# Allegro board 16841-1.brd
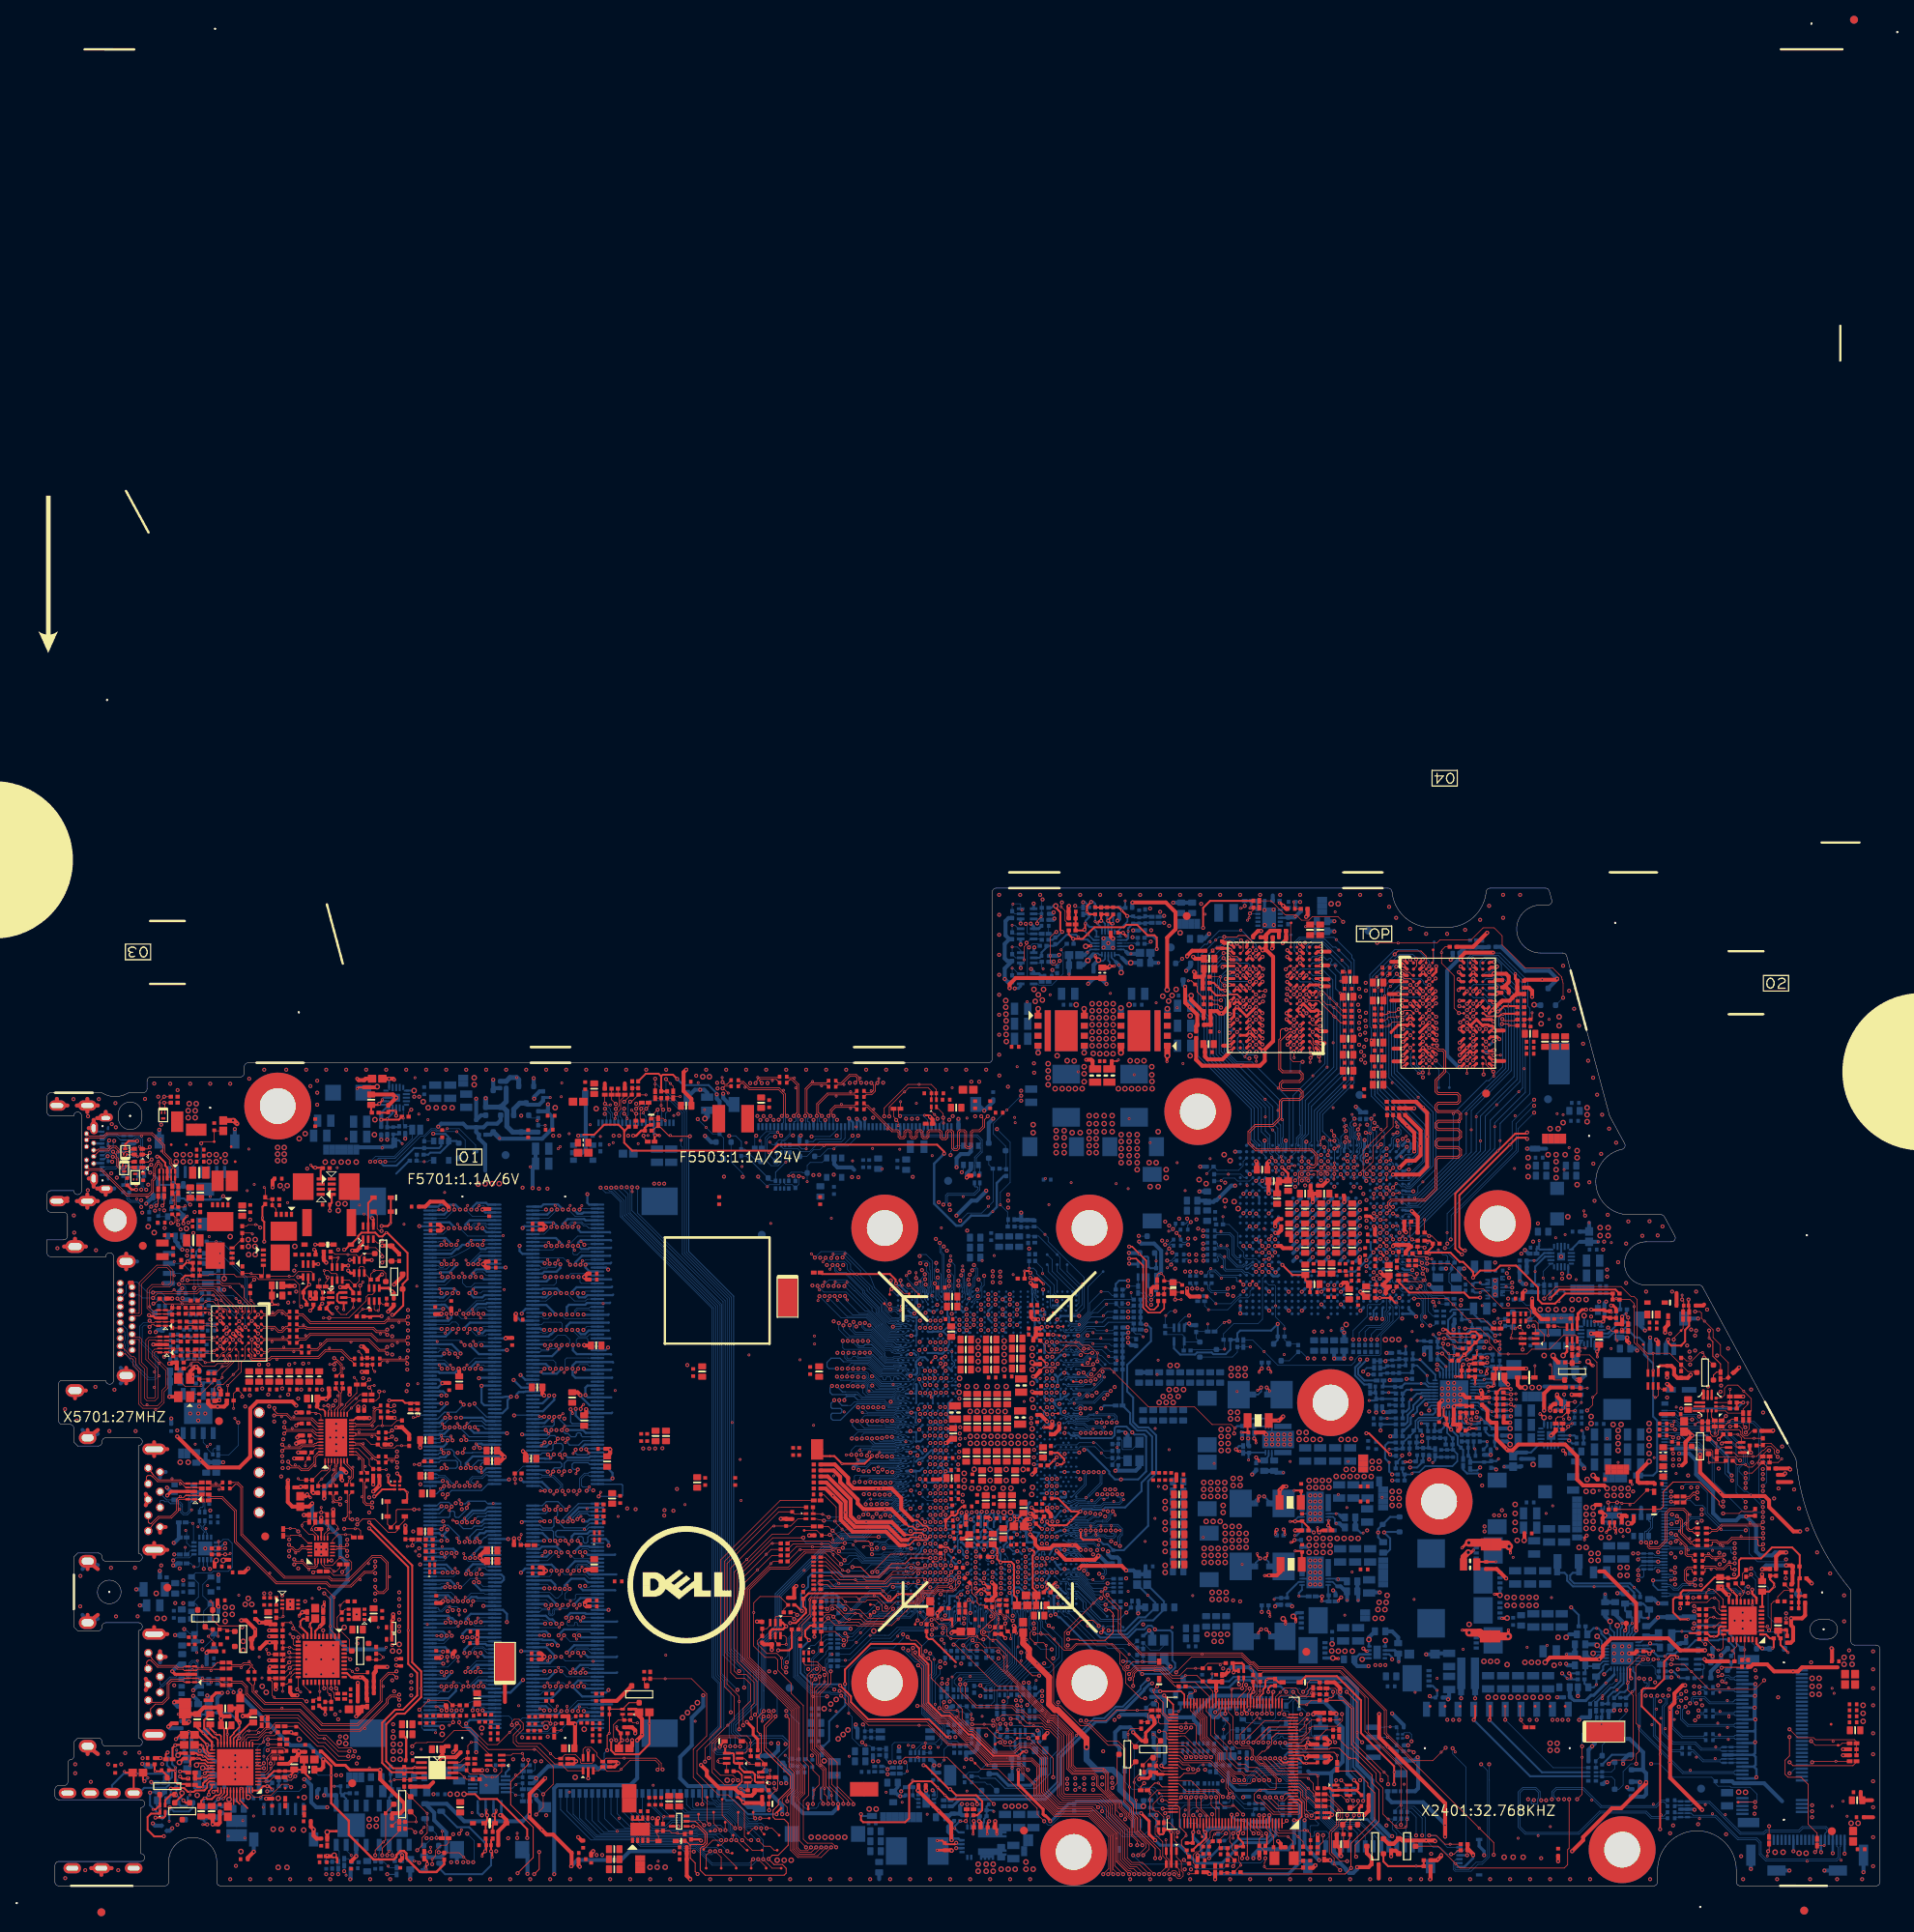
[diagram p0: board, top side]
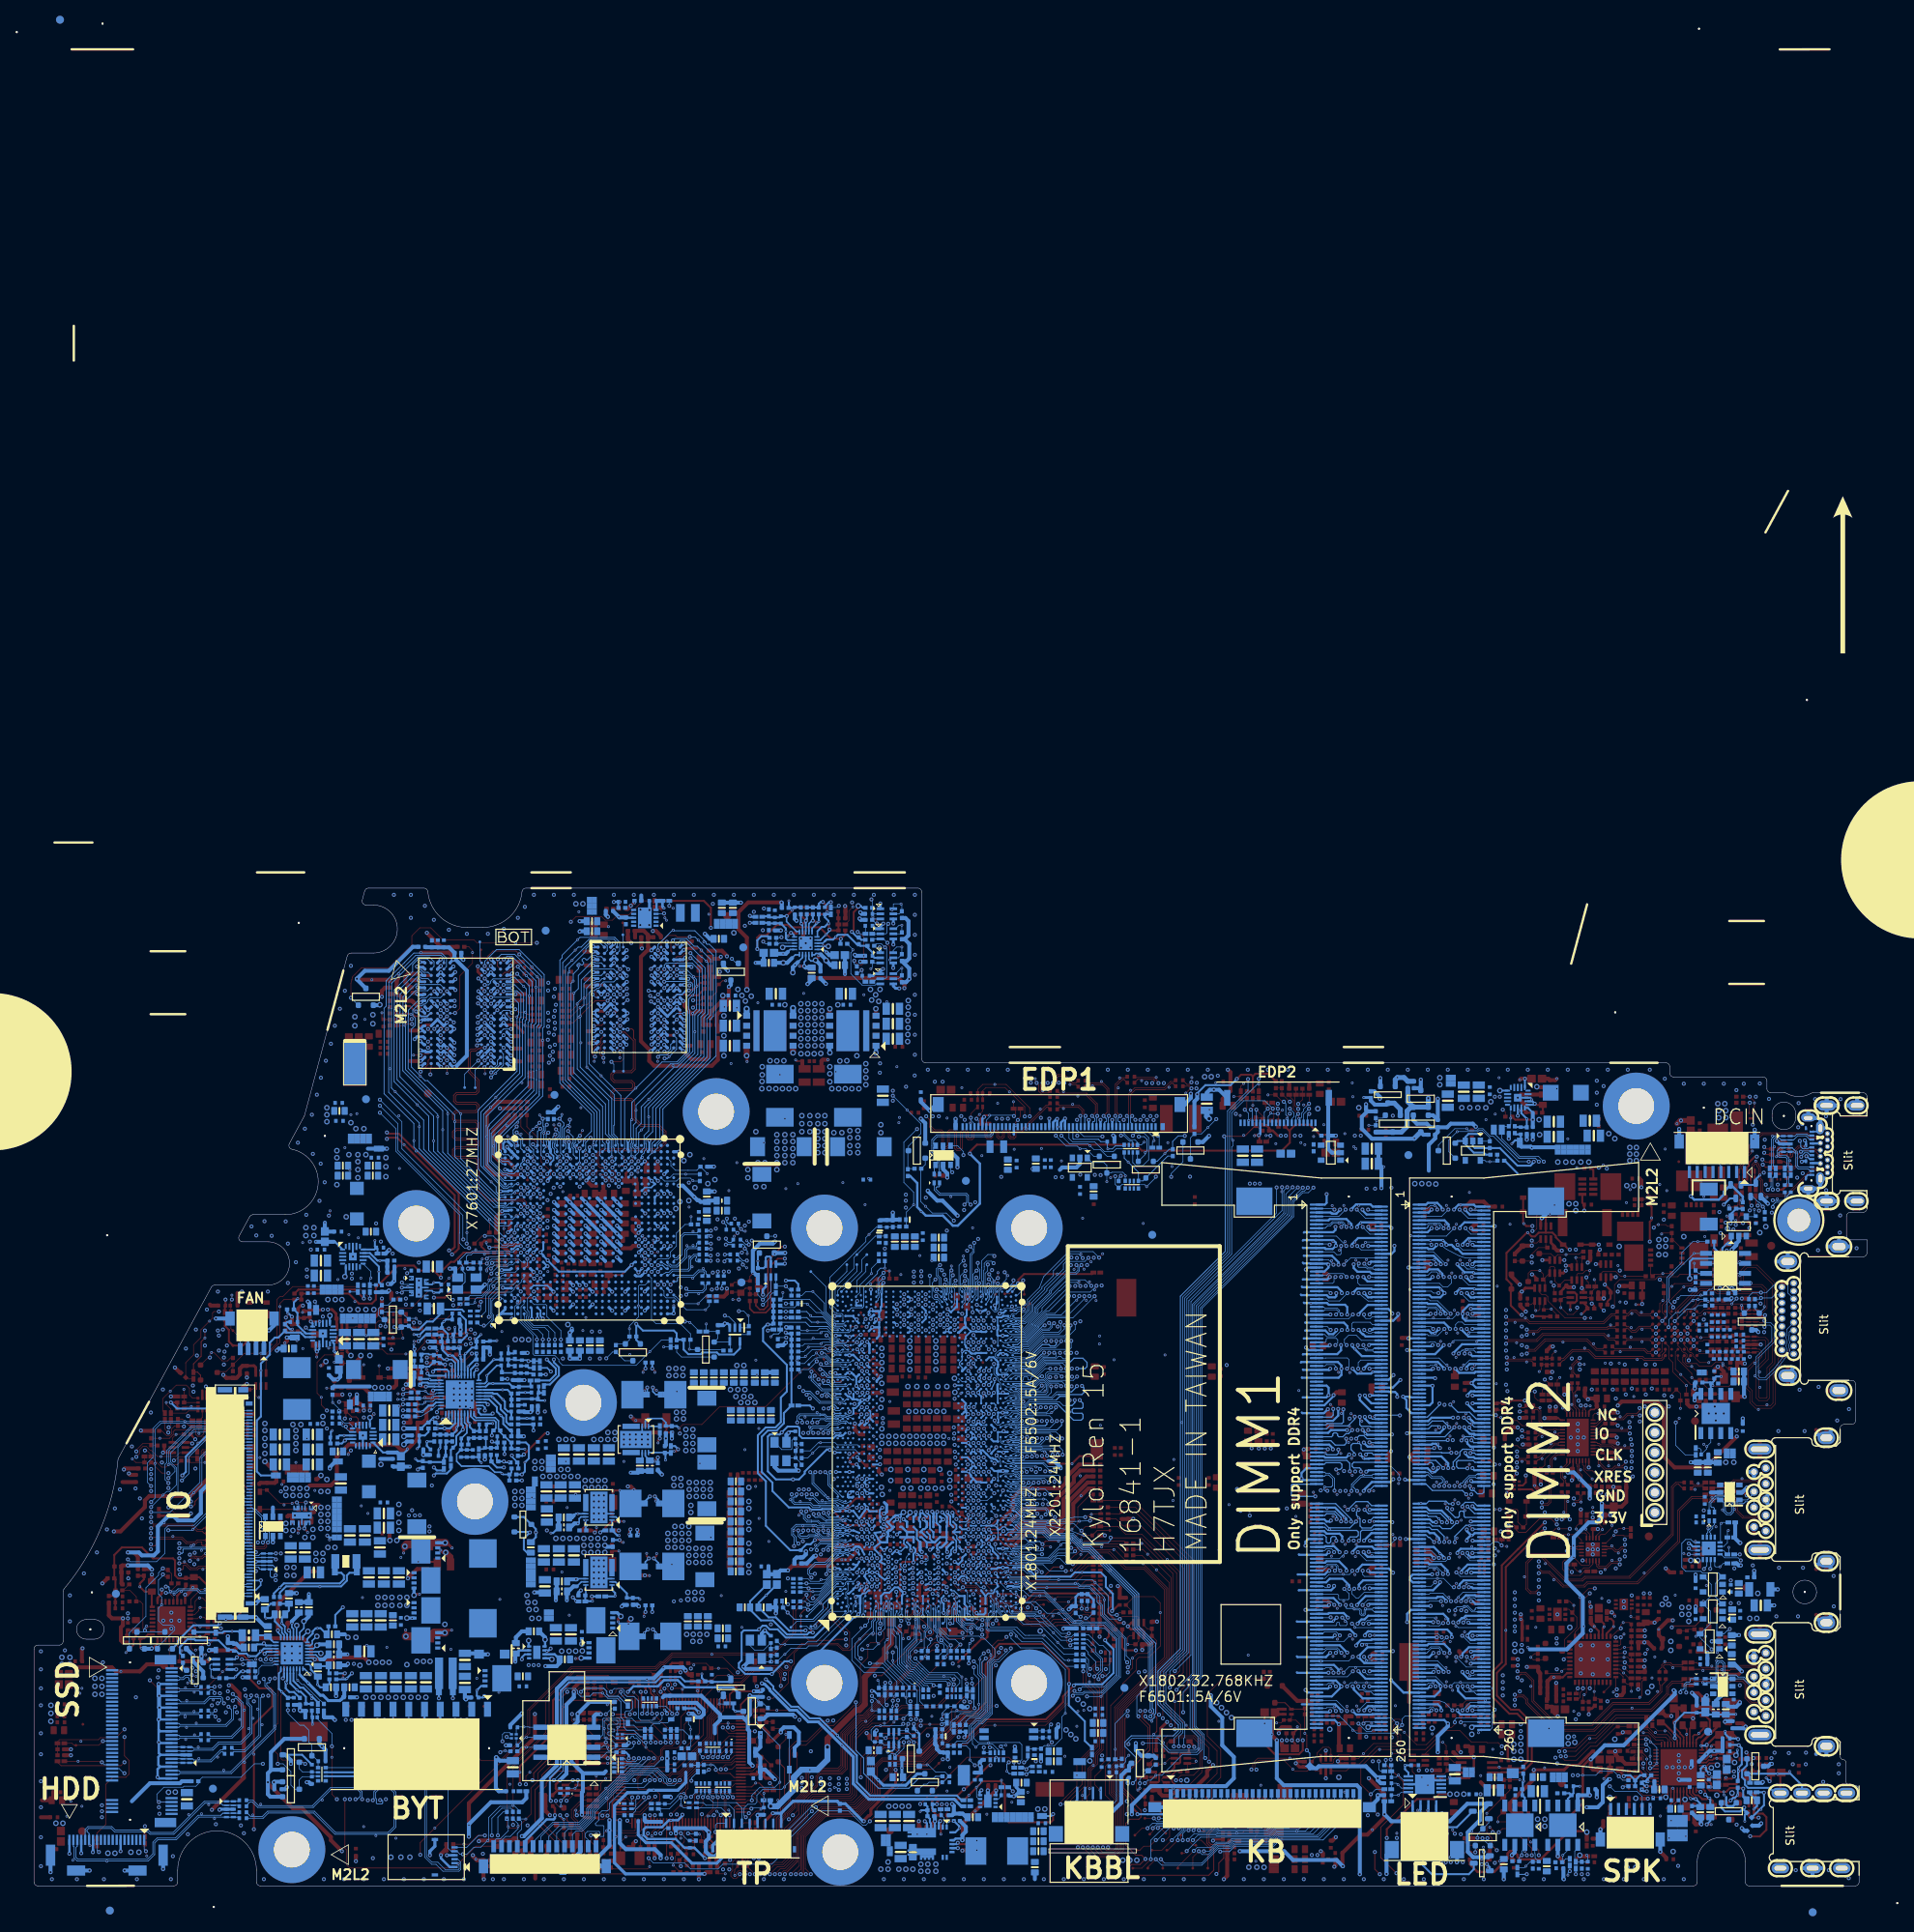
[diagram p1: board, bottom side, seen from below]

Outline 232.8 x 126.8 mm; copper layers: TOP, L2GND, L3, L4, L5VCC, L6, L7GND, BOTTOM. Coordinates in mm from the lower left corner of the outline.

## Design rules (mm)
constraint set DEFAULT: min track width 0.127, pair gap 0.102
net group AUDIO_12MIL: nets CPVEE TCH_RST#
net group AUDIO_BITCLK_50-MWS: nets CODEC_BITCLK_R HDA_BITCLK
net group CPU_RXN_C_DGPU_TXN0-DIFF1: nets CPU_RXN_C_DGPU_TXN0 CPU_RXP_C_DGPU_TXP0
net group CPU_RXN_C_DGPU_TXN1-DIFF1: nets CPU_RXN_C_DGPU_TXN1 CPU_RXP_C_DGPU_TXP1
net group CPU_RXN_C_DGPU_TXN2-DIFF1: nets CPU_RXN_C_DGPU_TXN2 CPU_RXP_C_DGPU_TXP2
net group CPU_RXN_C_DGPU_TXN3-DIFF1: nets CPU_RXN_C_DGPU_TXN3 CPU_RXP_C_DGPU_TXP3
net group DDR4_A_BA_40-MW: nets M_A_BA0 M_A_BA1
net group DDR4_A_BG_40-MW: nets M_A_BG0 M_A_BG1
net group DDR4_A_ODT10-MW: nets M_A_DIMA_ODT0 M_A_DIMA_ODT1
net group DDR4_B_BA_40-MW: nets M_B_BA0 M_B_BA1
net group DDR4_B_BG_40-MW: nets M_B_BG0 M_B_BG1
net group DDR4_B_ODT10-MW: nets M_B_DIMB_ODT0 M_B_DIMB_ODT1
net group DP_DATA0_R-DIFF1: nets DP_DATA0_N_R DP_DATA0_P_R
net group DP_DATA1_R-DIFF1: nets DP_DATA1_N_R DP_DATA1_P_R
net group DP_DATA2_R-DIFF1: nets DP_DATA2_N_R DP_DATA2_P_R
net group DP_DATA3_R-DIFF1: nets DP_DATA3_N_R DP_DATA3_P_R
net group EDP_AUX_CON-DIFF222: nets EDP_AUX EDP_AUX#
net group EDP_TX0_CON-DIFF224: nets EDP_TX0 EDP_TX0#
net group EDP_TX1_CON-DIFF278: nets EDP_TX1 EDP_TX1#
net group EDP_TX3_CON-DIFF230: nets EDP_TX3 EDP_TX3#
net group FAN_TACH: nets FAN1_TACH FAN_TACH1_C
net group HDMI_AUX_L-DIFF1: nets HDMI_AUXN_L HDMI_AUXP_L
net group HDMI_AUX_R-DIFF1: nets HDMI_AUXN_R HDMI_AUXP_R
net group HDMI_CLK-DIFF1: nets HDMI_CLK#_C HDMI_CLK_C
net group HDMI_CLK_R_C-DIFF: nets HDMI_CLK#_R_C HDMI_CLK_R_C
net group HDMI_DATA0_C-DIFF1: nets HDMI_DATA0#_C HDMI_DATA0_C
net group HDMI_DATA1_C-DIFF1: nets HDMI_DATA1#_C HDMI_DATA1_C
net group HDMI_DATA1_L_C-DIFF1: nets HDMI_DATA1#_L_C HDMI_DATA1_L_C
net group HDMI_DATA2_C-DIFF1: nets HDMI_DATA2#_C HDMI_DATA2_C
net group HDMI_DATA2_L_C-DIFF1: nets HDMI_DATA2#_L_C HDMI_DATA2_L_C
net group I2C_MUX_50: nets I2C_CLK_PD_MUX I2C_DATA_PD_MUX
net group MUX_INB_: nets MUX_INB_N MUX_INB_P
net group PCH_DPC_N0_CON-DIFF267: nets PCH_DPC_N0_C PCH_DPC_P0_C
net group PCH_DPC_N1_CON-DIFF266: nets PCH_DPC_N1_C PCH_DPC_P1_C
net group PCH_DPC_N2_CON-DIFF265: nets PCH_DPC_N2_C PCH_DPC_P2_C
net group PCH_DPC_N3_CON-DIFF264: nets PCH_DPC_N3_C PCH_DPC_P3_C
net group PCIE_TX_CON9-DIFF1: nets PCIE_TX_CON_N9 PCIE_TX_CON_P9
net group PCIE_TX_CON10-DIFF1: nets PCIE_TX_CON_N10 PCIE_TX_CON_P10
net group PCIE_TX_CON11-DIFF1: nets PCIE_TX_CON_N11 PCIE_TX_CON_P11
net group PCIE_TX_CPU6-DIFF1: nets PCIE_TX_CPU_N6 PCIE_TX_CPU_P6
net group POWER_15M: nets Q6205_Q Q6502_D
net group SATA_RX_CON0-DIFF269: nets SATA_RXN0_R SATA_RXP0_R
net group SIGNAL_V_F_8_OHM-MW: nets CFG3 XDP_DBRESET#
net group SIGNAL_V_F_10MIL: nets BEEP FAN_TACH1
net group SIGNAL_V_F_16.5_OHM-MWS: nets PCH_SMBCLK PCH_SMBDATA
net group SIGNAL_V_F_16.5_SVID-MWS: nets VR_SVID_CLK VR_SVID_DATA
net group SMBUS_10MIL: nets PBAT_SMBCLK1 PBAT_SMBDAT1
net group TYPEC_CON_RX1-DIFF270: nets TYPEC_CON_RXN1 TYPEC_CON_RXP1
net group TYPEC_CON_RX2-DIFF271: nets TYPEC_CON_RXN2 TYPEC_CON_RXP2
net group TYPEC_DPB_AUX_CON-DIFF259: nets DPB_AUXN_C DPB_AUXP_C
net group USB30_RX_C1-DIFF241: nets USB30_RXDN1_C USB30_RXDP1_C
net group USB30_RX_CON4-DIFF240: nets USB30_RX_CPU_N4_C USB30_RX_CPU_P4_C
net group USB30_TX_CON4-DIFF239: nets USB30_TX_CPU_N4_C USB30_TX_CPU_P4_C
net group USB_CON1-DIFF248: nets USB20_DN1_C USB20_DP1_C
net group USB_CON4-DIFF257: nets USB_CAMERA_N USB_CAMERA_P
net group USB_CON5-DIFF252: nets USB_CPU_PN5_C USB_CPU_PP5_C
net group USB_CON7-DIFF251: nets USB_CPU_PN7_C USB_CPU_PP7_C
net group XDP_BPM-MW: nets XDP_BPM0 XDP_BPM1
net group XDP_TCLK-MWS: nets XDP_TCK_JTAGX XDP_TCLK
net group AUDIO_BEEP_10MIL: nets AUD_HP1_JACK_L AUD_HP1_JACK_L1 AUD_HP1_JACK_R AUD_HP1_JACK_R1 AUD_PC_BEEP AUD_PC_BEEP_C AUD_PC_BEEP_R AUD_PORTA_L_R_B AUD_PORTA_R_R_B AUD_SENSE AUD_SENSE_A AUD_VREF CBN CBP HDA_SPKR_R JACK_PLUG JACK_PLUG_DET KBC_BEEP_R LINE1-L_C LINE1-L_R LINE1_L LINE1_R MIC2_VREFO_L MIC2_VREFO_R SPKR
net group AUDIO_DIGITAL_50-MWS: nets CODEC_SDOUT_R HDA_CODEC_SDIN0 HDA_RST# HDA_SDOUT HDA_SYNC SPK_I2C_CLK SPK_I2C_DATA
net group CFG_50-MWS: nets CFG4
net group CLK_50-MWS: nets SPI_CK_OUT_HDMI SPI_CLK_CPU SPI_CLK_ROM SPI_CLK_ROM_R SPI_CLK_ROM_TPM2 SUS_CLK SUSCLK
net group CLK_50R-MW: nets ESPI_CLK PCH_ESPI_CLK PEXTSTCLK_OUT PEXTSTCLK_OUT# VIDEO_CLK_XTAL_SS
net group COMP_20MIL: nets CPU_POPIRCOMP CSI2_COMP EMMC_RCOMP EOPIO_RCOMP PCH_POPIRCOMP SD_RCOMP SM_RCOMP_0 SM_RCOMP_1 SM_RCOMP_2 USBCOMP XCLK_BIASREF
net group CPU_50-MWS: nets H_PROCHOT#_R PQ4405_3 PWR_CHG_PROCHOT#
net group CPU_50R-MW: nets VGA_CORE_VID
net group DDR4_A_CMD_40-MW: nets M_A_A0 M_A_A1 M_A_A2 M_A_A3 M_A_A4 M_A_A5 M_A_A6 M_A_A7 M_A_A8 M_A_A9 M_A_A10 M_A_A11 M_A_A12 M_A_A13 M_A_A14 M_A_A15 M_A_A16 M_A_ACT_N M_A_ALERT_N M_A_PARITY
net group DDR4_A_DATA_00_50-MW: nets M_A_DQ0 M_A_DQ1 M_A_DQ2 M_A_DQ3 M_A_DQ4 M_A_DQ5 M_A_DQ6 M_A_DQ7
net group DDR4_A_DATA_01_50-MW: nets M_A_DQ8 M_A_DQ9 M_A_DQ10 M_A_DQ11 M_A_DQ12 M_A_DQ13 M_A_DQ14 M_A_DQ15
net group DDR4_A_DATA_02_50-MW: nets M_A_DQ16 M_A_DQ17 M_A_DQ18 M_A_DQ19 M_A_DQ20 M_A_DQ21 M_A_DQ22 M_A_DQ23
net group DDR4_A_DATA_03_50-MW: nets M_A_DQ24 M_A_DQ25 M_A_DQ26 M_A_DQ27 M_A_DQ28 M_A_DQ29 M_A_DQ30 M_A_DQ31
net group DDR4_A_DATA_04_50--MW: nets M_A_DQ32 M_A_DQ33 M_A_DQ34 M_A_DQ35 M_A_DQ36 M_A_DQ37 M_A_DQ38 M_A_DQ39
net group DDR4_A_DATA_05_50-MW: nets M_A_DQ40 M_A_DQ41 M_A_DQ42 M_A_DQ43 M_A_DQ44 M_A_DQ45 M_A_DQ46 M_A_DQ47
net group DDR4_A_DATA_06_50-MW: nets M_A_DQ48 M_A_DQ49 M_A_DQ50 M_A_DQ51 M_A_DQ52 M_A_DQ53 M_A_DQ54 M_A_DQ55
net group DDR4_A_DATA_07_50-MW: nets M_A_DQ56 M_A_DQ57 M_A_DQ58 M_A_DQ59 M_A_DQ60 M_A_DQ61 M_A_DQ62 M_A_DQ63
net group DDR4_B_CMD_40--MW: nets M_B_A0 M_B_A1 M_B_A2 M_B_A3 M_B_A4 M_B_A5 M_B_A6 M_B_A7 M_B_A8 M_B_A9 M_B_A10 M_B_A11 M_B_A12 M_B_A13 M_B_A14 M_B_A15 M_B_A16 M_B_ACT_N M_B_ALERT_N M_B_PARITY
net group DDR4_B_DATA_00_50-MW: nets M_B_DQ0 M_B_DQ1 M_B_DQ2 M_B_DQ3 M_B_DQ4 M_B_DQ5 M_B_DQ6 M_B_DQ7
net group DDR4_B_DATA_01_50-MW: nets M_B_DQ8 M_B_DQ9 M_B_DQ10 M_B_DQ11 M_B_DQ12 M_B_DQ13 M_B_DQ14 M_B_DQ15
net group DDR4_B_DATA_02_50-MW: nets M_B_DQ16 M_B_DQ17 M_B_DQ18 M_B_DQ19 M_B_DQ20 M_B_DQ21 M_B_DQ22 M_B_DQ23
net group DDR4_B_DATA_03_50-MW: nets M_B_DQ24 M_B_DQ25 M_B_DQ26 M_B_DQ27 M_B_DQ28 M_B_DQ29 M_B_DQ30 M_B_DQ31
net group DDR4_B_DATA_04_50-MW: nets M_B_DQ32 M_B_DQ33 M_B_DQ34 M_B_DQ35 M_B_DQ36 M_B_DQ37 M_B_DQ38 M_B_DQ39
net group DDR4_B_DATA_05_50-MW: nets M_B_DQ40 M_B_DQ41 M_B_DQ42 M_B_DQ43 M_B_DQ44 M_B_DQ45 M_B_DQ46 M_B_DQ47
net group DDR4_B_DATA_06_50-MW: nets M_B_DQ48 M_B_DQ49 M_B_DQ50 M_B_DQ51 M_B_DQ52 M_B_DQ53 M_B_DQ54 M_B_DQ55
net group DDR4_B_DATA_07_50-MW: nets M_B_DQ56 M_B_DQ57 M_B_DQ58 M_B_DQ59 M_B_DQ60 M_B_DQ61 M_B_DQ62 M_B_DQ63
net group DDR4_CKE_40-MW: nets M_A_CKE0 M_A_CKE1 M_A_CS#0 M_A_CS#1 M_B_CKE0 M_B_CKE1 M_B_CS#0 M_B_CS#1
net group ESPI: nets ESPI_ALERT# ESPI_IO0 ESPI_IO1 ESPI_IO2 ESPI_IO3 PCH_ESPI_IO0 PCH_ESPI_IO1 PCH_ESPI_IO2 PCH_ESPI_IO3
net group FBA_VREF: nets FBA_VREF_FET_H FBA_VREF_FET_L FBA_VREFC0 FBA_VREFC1 FBA_VREFD_H FBA_VREFD_L
net group GND: nets MIC_GND
net group HDA_CODEC_BITCLK: nets HDA_CODEC_BITCLK
net group I2C_TOUCH_PAD-MWS: nets I2C0_SCL_TCH_PAD I2C0_SDA_TCH_PAD TCH_I2C_SCL TCH_I2C_SDA
net group JTAG-MW: nets PCH_JTAG_TCK PCH_JTAG_TDI PCH_JTAG_TDO PCH_JTAG_TMS
net group KBC: nets KSI0 KSI1 KSI2 KSI3 KSI4 KSI5 KSI6 KSI7 KSO0 KSO1 KSO2 KSO3 KSO4 KSO5 KSO6 KSO7 KSO8 KSO9 KSO10 KSO11 KSO12 KSO13 KSO14 KSO15 KSO16
net group LCD_BKLT: nets BKLT_CTRL L_BKLT_CTRL LCD_BRIGHTNESS
net group LED: nets BAT1_LED# BAT2_LED# BATT_WHITE_LED# BATT_WHITE_LED_R# CAP_LED# CAP_LED_R# CHG_AMBER_LED#
net group LED_20MIL: nets AMBER_LED_BAT BAT_AMBER BAT_WHITE CAP_LED CAP_LED#_R CAP_LED_Q CHG_AMBER_LED_R# WHITE_LED_BAT
net group OTHER_4MIL: nets 1D05V_VGA_S0_DISCHG 1D35V_VGA_S0_DISCHG 3D3V_VGA_S0_DISCHG 3V3_AON_S0_DISCHG 5V_VCONN_EN A5_TP A67_TP A70_TP AC_PRESENT AD_IA AUDIO_47 AUX_EN_WOWL AUX_EN_WOWL_EC AUX_ON BKLT_IN_EC BLON_OUT_C BLUETOOTH_EN BOARD_ID BOARD_ID1 BOARD_ID2 BREATH_LED# CAD_SNK CCG4_FLIP# CCG4_GPIO21 CCG4_I2C_INT# CCG4_ID_1 CCG4_ID_2 CCG4_OVP_TRIP_P1 CCG4_OVP_TRIP_P1_G CLK_PCIE_LAN_REQ# CLK_PCIE_NVME_REQ# CLK_PCIE_PEG_REQ# CLK_PCIE_SD_REQ# CLK_PCIE_TBT_REQ# CLK_PCIE_WLAN_REQ# CLKRUN#_EC CPU_DP1_HPD CPU_DP1_HPD_R CPU_DP_HPD_MUX CTL1 CTL2 CTL3 DBC_EN_R DBC_PANEL_EN DGPU_PWR_EN DGPU_PWR_EN# DGPU_PWR_EN_L DGPU_PWROK DGPUHOT# DOCK_USB_EN_A DOCK_USB_EN_B DPEQ0_A1 DPEQ1 DVSS EAPD# EC_VCIN1# EDP_DISP_UTIL EDP_HPD EDP_HPD_CONN EQ0 EQ1 FALL_INT2 FAN_PWM1_C FB_VREF FBA_DEBUG0 FBA_DEBUG1 FFS_INT1 FFS_INT2 FFS_INT2_Q FFS_INT2_Q_R FPR_SCAN# GC6_THM_DIS# GC6_THM_DIS#_EC GPD11/LANPHYPC GPU_PWR_LEVEL GSEN2_INT1_ISH GSEN2_INT2 GSEN2_INT2_ISH GSEN_INT1 GSEN_INT1_ISH GSEN_INT2 GSEN_INT2_ISH GYRO_DRDY_ISH GYRO_INT GYRO_INT_C GYRO_INT_ISH GYRO_INT_P11 H_CATERR# H_PECI_CPU HDD_DEVSLP_R HDMI_CEC HDMI_CEC_C HOST_DEBUG_TX HOST_DEBUG_TX_CON HPD_HDMI_CON HPDIN HW_ACAV_IN HW_ACAVIN_NB I2CEN I_ADP I_BATT ICSP_CLK ICSP_CLR ICSP_DAT IE_DELAY_G IE_DELAY_S ILIM_HI ILIM_LO ILIM_SEL INT2_SELECT INT#_TYPEC_R IR_CAM_DET# IR_CAMERA_DET#_R ISH_KB_DISABLE KB_DISABLE_CPU_R KB_LED_BL_DET KB_LED_DET_C KB_LED_PWM KBC_PWRBTN# L_BKLT_EN L_BKLT_EN_L LAN_WAKE# LANWAKE# LANWAKE#_IC LCD_CBL_DET# LCD_TST_C LCD_VCC_TEST_EN LID_CL_SIO_TAB# M2_SSD_PEDET MASK_SATA_LED# ME_FWP MODEL_ID MSATA_DEVSLP_R MSATA_RST# MSM# MUX_ENA_L MUX_ENB_L MUX_HPD_PD MUX_SAI MUX_SAO MUX_SBI MUX_SBO N12P_JTAG_TCK N12P_JTAG_TDI N12P_JTAG_TDO N12P_JTAG_TMS N12P_JTAG_TRST N12P_XTAL_OUTBUFF NB_MODE# NB_MUTE# NRB_BIT P2800_VGA_DXN P2800_VGA_DXP P_SYS PANEL_BKEN PBAT_PRES1# PBAT_PRES# PCH_BATLOW# PCH_THERMTRIP# PCIE_WAKE# PCIE_WAKE#_CPU PD4403_A PD4403_K PD_VBUS_C_CTRL1_R PEX_TERMP PIRQA# POWER_SW_IN# PQ4405_2 PQ4405_5 PQ4405_6 PQ4408_C PQ4408_E PRIM_PWRGD PROC_SELECT# PROCHOT PROJECT_ID0 PROJECT_ID1 PROJECT_ID2 PROJECT_ID3 PS175_CEC_EN PS175_GPIO0 PS175_GPIO2 PS175_PD# PS175_RST# PS_ID_R PS_ID_R1 PSYS PWR_0D6V_S3EN PWR_0D6V_S5EN PWR_1D05V_FB_R PWR_2D5V_EN PWR_3D3V_EN1 PWR_5V_EN1 PWR_5V_EN1_R PWR_CHG_ACOK PWR_VDDQ_EN Q7601_G Q9102_G RESET_OUT#_G REXT RUNPWROK SA0_CHA_DIM0 SA0_CHB_DIM0 SA1_CHA_DIM0 SA1_CHB_DIM0 SA2_CHA_DIM0 SA2_CHB_DIM0 SATA_LED# SERIRQ_TPM SIO_EXT_SMI# SIO_EXT_WAKE# SIO_PWRBTN# SIO_SLP_S3#_EC SKTOCC# SM_INTRUDER# SMB_ALERT# SML0_ALERT# SML1ALERT# SPK_ID SSD_DEVSLP SSEQ0_A0 SSEQ1 SYS_PRES1# SYSPWR_PRES TCH_INTR# TCH_REPORT_SWITCH TESTMODE TOUCH_DETECT TOUCH_PAD_INTR# TOUCH_PANEL_PD# TOUCH_REPORT_SW TP_VPPNC3 TP_VPPNC4 TP_VPPNC5 TP_VPPNC6 TP_VPPNC7 TP_VPPNC8 TP_WAKE_KBC# TPM_GPIO0 TPM_GPIO2 TPM_GPIO4 TPM_ID TPM_SPI_IRQ# TPS70933_EN_G U4006_CT UART_2_CRXD_DTXD UART_2_CRXD_DTXD_CON UART_2_CTXD_DRXD UART_2_CTXD_DRXD_CON USB2_ID USB2_VBUSSENSE USB_OC1# USB_OC2# USB_POWERSHARE_VBUS_EN USB_PWR_SHR_EN_L# V0.85A_VID0 V0.85A_VID1 VBUS_PRODECT# VBUS_PRODECT_G VBUS_SENSE VCCG0 VCCG1 VCCSTG_EN_L VCONN_MON_P1 VCREF0 VGA_CORE_DISCHG VPP1 VPP2 VR_RDY VRALERT# VRAM_ID1 VRAM_ID2 VREF_CPU WIFI_RF_EN ZVM#
net group PLATFORM: nets 1D0V_S5_PWRGD 1D2V_HDMI_EN 1D2V_HDMI_EN_R 1D05V_VGA_EN 1D05V_VGA_EN# 1D05V_VGA_S0_PWRGD 1D8V_EN# 1D8V_EN_R# 1D35V_PGOOD 1D35V_VGA_EN 1D35V_VGA_EN# 3V5V_S0_ON 3V_5V_POK# 3V_5V_POK_C +SDC_IN_SW +SDC_IN_SW_R1 CPU_DP2_HPD CPU_DP_HPD_R DGPU_HOLD_RST# DGPU_PWR_EN_R EDP_VDD_EN FBA_MF1 FBA_MF2 FBA_MF3 FBA_MF4 FBA_SEN0 FBA_SEN2 GC6_FB_EN_GPU GC6_FB_EN_MCP GPIO5_GC6_PWR_EN GPIO5_GC6_PWR_EN# GPIO5_GC6_PWR_EN_GPU GPIO5_GC6_PWR_EN_R GPIO9_ALERT GPIO10_FBVREF GPU_CLKREQ# GPU_EVENT# GPU_EVENT_GPU# GPU_EVENT_MCP# GPU_PEX_RST# GPU_PEX_RST_HOLD GPU_PEX_RST_HOLD_GPU# GSENSOR_CS GSENSOR_SDO H_CPUPWRGD H_VCCST_PWRGD IC_DELAY LVDS_VDD_EN_R ME_SUS_PWR_ACK_R OVERT_GPU# PCH_PLTRST# PCH_RSMRST# PD_SWD_CLK PD_SWD_IO PD_VBUS_C_CTRL1 PD_VBUS_C_CTRL1_A PD_VBUS_DISCHG PD_VBUS_P_CTRL1 PD_VBUS_P_CTRL1_R PD_VBUS_R PD_VCCD PD_XRES PM_RSMRST#_M PM_RSMRST#_R PTP_DIS# PWR_0D6V_VCNTL PWR_1D0V_EN PWR_1D0V_PG PWR_1D05V_PGOOD PWR_1D8V_EN PWR_1D8V_POK PWR_1D35V_EN PWR_2D5V_PG PWR_3D3V_EN PWR_VGA_CORE_EN# RSMRST_PWRGD# RTCRST_ON SM_DRAMRST# SM_PGCNTL SM_PGCNTL_R SRTC_RST# STRAP0 STRAP1 STRAP2 STRAP3 STRAP4 STRAP_REF0_GND_N9 SUSACK#_R SYS_PEX_RST_MON# SYS_PEX_RST_MON_GPU# TP_ON#_GATE TPS70933_EN TS#_DIMM0_1 TS#_DIMM1_1 USB_ADT_SW USB_ADT_SW_R USB_EN# USB_TYPEC_R VCCSTG_EN_R VCCSTU_EN_R VGA_CORE_PSI
net group POWER_10M: nets 1.8V_RUN_FB 3D3V_RTC_SYS 3D3V_TPM_1 3D3V_VGA_CT_1 3V3_AON_CT_2 3V5V_CT1 3V5V_CT2 +3V_1D8V_AVDD +3V_1D8V_AVDD_IO +UZ12_TPM +VCCAMPHYPLL_1P0 +VCCAPLL_1P0 +VCCCLK2 +VCCCLK4 +VCCCLK5 +VCCDSW_1P0 +VCCPAZIO +VCCPRTC_3P3 +VCCST_CPU +VCCSTG DDR_VREF_S3 FB_CLAM FBA_ZQ0 FBA_ZQ1 FBA_ZQ2 FBA_ZQ3 GPU_NC_F11 LDO1_CAP LDO2_CAP LDO3_CAP MIC_CAP PWR_1D0V_BT PWR_1D0V_PFM PWR_1D0V_SS PWR_1D0V_TON PWR_1D35V_BYP PWR_1D35V_IMAX PWR_2D5V_FB PWR_3D3V_FB PWR_3D3V_VOUT PWR_5V_EN PWR_5V_FB PWR_5V_FB_A PWR_5V_VCC PWR_5V_VOUT PWR_CHG_AIN PWR_CHG_AMON PWR_CHG_ASGATE PWR_CHG_BATGONE PWR_CHG_BGATE PWR_CHG_COMP PWR_CHG_COMP_R PWR_CHG_CSIN PWR_CHG_CSIN_R PWR_CHG_CSIP PWR_CHG_CSIP_R PWR_CHG_CSON PWR_CHG_CSON_R PWR_CHG_CSOP PWR_CHG_CSOP_R PWR_CHG_OTGEN PWR_CHG_OTGPG PWR_CHG_PROCHOT#_R PWR_CHG_PROG PWR_CHG_SNB PWR_CHG_VDDP PWR_VCCGT_COMP PWR_VCCGT_COMP1 PWR_VCCGT_FB PWR_VCCGT_FCCM# PWR_VCCGT_FCCM#_RA PWR_VCCGT_FCCM#_RB PWR_VCCGT_IMON PWR_VCCGT_ISUMN_GB PWR_VCCGT_ISUMN_P_1 PWR_VCCGT_ISUMN_P_2 PWR_VCCGT_ISUMN_RC PWR_VCCGT_ISUMNB PWR_VCCGT_ISUMP_GB PWR_VCCGT_NTC PWR_VCCGT_NTC1 PWR_VCCGT_PWMA PWR_VCCGT_PWMA_RA PWR_VCCGT_PWMB PWR_VCCGT_PWMB_RA PWR_VCCGT_RTN PWR_VCCGT_SNB1 PWR_VCCGT_SNB2 PWR_VCCGT_VCCDA PWR_VCCGT_VCCDB PWR_VCCSA_COMP PWR_VCCSA_COMP_RC PWR_VCCSA_FCCM PWR_VCCSA_IMON PWR_VCCSA_ISUMN_P_1 PWR_VCCSA_ISUMN_P_2 PWR_VCCSA_ISUMN_RC PWR_VCCSA_ISUMNB PWR_VCCSA_RTN PWR_VCORE_COMP PWR_VCORE_COMP1 PWR_VCORE_FCCM# PWR_VCORE_FCCM#_R PWR_VCORE_IMON PWR_VCORE_ISUMN_P_1 PWR_VCORE_ISUMN_P_2 PWR_VCORE_ISUMN_RC PWR_VCORE_ISUMNA PWR_VCORE_NTC PWR_VCORE_NTC1 PWR_VCORE_PROG1 PWR_VCORE_PROG2 PWR_VCORE_PWM_R PWR_VCORE_RTN PWR_VCORE_SNB PWR_VCORE_VCC_R PWR_VCORE_VIN PWR_VCORE_VRHOT# PWR_VDDQ_ILMT PWR_VDDQ_VCC PWR_VGA_CORE_EN PWR_VGA_CORE_PSI PWR_VGA_CORE_REFIN PWR_VGA_CORE_VID PWR_VGA_CORE_VREF Q6204_G REFIN_VREF TPM_VDD14 TPM_VDD22 TPM_VSB TYPEC_5V TYPEC_5V_L TYPEC_5V_SW_R VCCRTCEXT
net group POWER_10M_POWER: nets 1D2V_HDMI_FB AC_IN#_G AD_OFF_L PWR_1D0V_FB PWR_1D0V_FB_A PWR_3D3V_FB2 PWR_CHG_ACIN PWR_CHG_DCIN PWR_CHG_DCIN_R PWR_VCCGT_FB1 PWR_VCCGT_FB2 PWR_VCCGT_FB_RC PWR_VCCSA_FB PWR_VCCSA_FB1 PWR_VCCSA_FB2 PWR_VCCSA_FB_RC PWR_VCCSA_PWM PWR_VCORE_FB PWR_VCORE_FB1 PWR_VCORE_FB2 PWR_VCORE_FB_RC PWR_VCORE_PWM PWR_VDDQ_FB PWR_VDDQ_FB_A PWR_VGA_CORE_REFADJ PWR_VGA_CORE_SS PWR_VGA_CORE_TON PWR_VGA_CORE_TON_1 USB_TYPEC_SW VCCSA_SENSE VDD VSS_AY71 VSSSA_SENSE
net group POWER_20M: nets 1D8V_S0 1D8V_S5_KBC 3D3V_AUX_S5 5V_AUX_S5 +RTC_VCC AUX_MODE PD_CC1 PD_CC2 PWR_1D05V_EN PWR_1D35V_VFB PWR_1D35V_VFB1 PWR_3D3V_BOOT PWR_3D3V_BOOT_A PWR_5V_BOOT PWR_5V_BOOT_A PWR_CHG_BOOT1 PWR_CHG_BOOT2 PWR_CHG_BT1_R PWR_CHG_BT2_R PWR_VCCGT_BOOTRA PWR_VCCGT_BOOTRB PWR_VCORE_BOOTR PWR_VDDQ_BOOT PWR_VDDQ_BOOT_A RTC_AUX_S5 VCC3PD VDDIO
net group POWER_20M_POWER: nets CPVDD KB_BL_CTRL# PWR_1D35V_BOOT PWR_1D35V_BOOT_R PWR_VCCGT_BOOTA PWR_VCCGT_BOOTA_RC PWR_VCCGT_BOOTB PWR_VCCGT_BOOTB_RC PWR_VCCSA_BST PWR_VCCSA_BST_RC PWR_VCORE_BOOT PWR_VCORE_BOOT_RC PWR_VCORE_VCC PWR_VGA_CORE_BOOT1 PWR_VGA_CORE_BOOT1_1 PWR_VGA_CORE_BOOT2 PWR_VGA_CORE_BOOT2_1 PWR_VGA_SNUB1 PWR_VGA_SNUB2
net group POWER_25M: nets PQ3802_1 PS_ID_R2 PSID_DISABLE#_R_C
net group POWER_40M: nets 5V_VCONN_P1_CCG4 FB_CAL_PD_VDDQ FB_CAL_PU_GND FB_CAL_TERM_GND
net group POWER_40M_POWER: nets PWR_CHG_HG1_R PWR_CHG_HG2_R PWR_CHG_LGATE1 PWR_CHG_LGATE2 PWR_CHG_UGATE1 PWR_CHG_UGATE2 PWR_VCCSA_DRVH PWR_VCCSA_DRVL PWR_VGA_CORE_LGATE1 PWR_VGA_CORE_LGATE2 PWR_VGA_CORE_UGATE1 PWR_VGA_CORE_UGATE2
net group POWER_160M: nets RT8812_PVCC
net group POWER_240M_POWER: nets PWR_1D05V_SVIN
net group POWER_320M_POWER: nets PWR_CHG_VBAT1
net group POWER_2680M_POWER: nets U22_POWER_K52
net group REF10M: nets VR_CAP
net group SIGNAL_V_F_4MIL: nets 3V_5V_POK AC_DIS AC_DIS_R CLKRUN# FAN1_PWM GSEN2_INT1 GSEN2_INT1_C GSEN2_INT2_C GYRO_DRDY HDD_DEVSLP ITP_PMODE KB_DET# LCD_TST LID_CL_SIO# PLT_RST# PLT_RST#_Q_TPM2 RESET_OUT# RTC_DET# USB_OC0# USB_OC3# VR_EN
net group SIGNAL_V_F_5MIL: nets 1D2V_VTT_PWRGD 3V_5V_EN ACOK# ALWON DDR4_DRAMRST# EC_SLP_S0IX# EXT_PWR_GATE# GC6_FB_EN PANEL_BKEN_EC PCH_DPWROK PM_PCH_PWROK PM_RSMRST# RTC_RST# SIO_SLP_S0# SIO_SLP_S3# SIO_SLP_S4# SYS_PWROK TOUCH_PANEL_INTR# TP_EN#
net group SIGNAL_V_F_10MIL-2: nets ACOK_IN_M DC_IN_OK DC_IN_OK# DC_IN_OK_R
net group SIGNAL_V_F_14_OHM-MW: nets VR_SVID_ALERT#
net group SIGNAL_V_F_15_OHM-MW: nets H_PECI
net group SIGNAL_V_F_50_OHM-MWS: nets H_PROCHOT# MEM_SMBCLK MEM_SMBDATA
net group SIGNAL_V_F_50OHM: nets HDA_CODEC_SDOUT HDA_CODEC_SYNC HDA_SDIN0
net group SMBUS_50-MWS: nets CCG4_I2C_SCL CCG4_I2C_SDA CLK_TP_SIO CPU_DP1_CTRL_CLK CPU_DP1_CTRL_DATA CPU_DP2_CTRL_CLK CPU_DP2_CTRL_DATA DAT_TP_SIO DDC_CLK_HDMI DDC_CLK_PH1 DDC_DATA_HDMI DDC_DATA_PH2 DMIC_CLK DMIC_CLK_C DMIC_CLK_R DMIC_DATA DMIC_DATA_C DMIC_DATA_R GPU_I2CA_SCL GPU_I2CA_SDA GPU_ROM_SCLK GPU_ROM_SI GPU_ROM_SO GPU_THM_SMBCLK GPU_THM_SMBDAT I2C0_SCL_R I2C0_SCL_TCH_PNL I2C0_SDA_R I2C0_SDA_TCH_PNL I2C1_SCL I2C1_SDA I2C_CLK_PD I2C_DATA_PD I2CB_SCL I2CB_SDA I2CC_SCL I2CC_SDA ISH_I2C0_SCL ISH_I2C0_SDA PBAT_CHG_SMBCLK PBAT_CHG_SMBDAT PS175_CSCL PS175_CSDA SENSOR_I2C_SCL SENSOR_I2C_SCL_2G SENSOR_I2C_SDA SENSOR_I2C_SDA_2G SMBC_THERM_NV SMBD_THERM_NV SML0_SMBCLK SML0_SMBDATA SML1_SMBCLK SML1_SMBDATA THM_SML1_CLK THM_SML1_DATA TPCLK_C TPDATA_C TYPEC_SMBCLK TYPEC_SMBDA
net group SPI_50-MWS: nets HOLD#_HDMI SIO_EXT_SCI# SIO_RCIN# SPI_CS2#_R_TPM2 SPI_CS_CPU_N0 SPI_CS_CPU_N1 SPI_CS_HDMI SPI_CS_ROM_N0 SPI_D_IN_HDMI SPI_D_OUT_HDMI SPI_HOLD_CPU SPI_HOLD_ROM SPI_HOLD_ROM_R SPI_IRQ#_TPM2 SPI_SI_CPU SPI_SI_ROM SPI_SI_ROM_R SPI_SI_ROM_TPM2 SPI_SO_CPU SPI_SO_ROM SPI_SO_ROM_R SPI_SO_ROM_TPM2 SPI_WP_CPU SPI_WP_ROM SPI_WP_ROM_R SPI_WR_PROT_HDMI
net group SPI_CS_ROM_N1: nets SPI_CS_ROM_N1
net group SVID-MW: nets H_CPU_SVIDALRT# H_CPU_SVIDCLK H_CPU_SVIDDAT PWR_VCORE_ALERT# PWR_VCORE_SCLK PWR_VCORE_SDIO
net group T8-MW: nets CMP_VIN0 CMP_VIN0_R CMP_VIN1 CMP_VOUT0 VD_IN1_C
net group TESTPD_4MIL: nets AV1_TP AV71_TP B71_TP BA1_TP BA2_TP BA71_TP BB67_TP BB70_TP C1_TP E71_TP RSVD_F65 RSVD_G65
net group THERM_SHUTDOWN: nets ALERT# PURE_HW_SHUTDOWN# T_CRIT# THERM_SYS_SHDN#
net group TYPEC_10MIL: nets 3D3V_MUX2
net group VRAM_CMD_45R-MWS: nets FBA_CMD0 FBA_CMD1 FBA_CMD2 FBA_CMD3 FBA_CMD4 FBA_CMD5 FBA_CMD6 FBA_CMD7 FBA_CMD8 FBA_CMD9 FBA_CMD10 FBA_CMD11 FBA_CMD12 FBA_CMD13 FBA_CMD14 FBA_CMD15 FBA_CMD16 FBA_CMD17 FBA_CMD18 FBA_CMD19 FBA_CMD20 FBA_CMD21 FBA_CMD22 FBA_CMD23 FBA_CMD24 FBA_CMD25 FBA_CMD26 FBA_CMD27 FBA_CMD28 FBA_CMD29 FBA_CMD30 FBA_CMD31
net group VRAM_DBI_45R-MWS: nets FBA_DQM0 FBA_DQM1 FBA_DQM2 FBA_DQM3
net group VRAM_DQ_45R-MW: nets FBA_CLK0_MIDPT FBA_CLK1_MIDPT FBA_D0 FBA_D1 FBA_D2 FBA_D3 FBA_D4 FBA_D5 FBA_D6 FBA_D7 FBA_D8 FBA_D9 FBA_D10 FBA_D11 FBA_D12 FBA_D13 FBA_D14 FBA_D15 FBA_D16 FBA_D17 FBA_D18 FBA_D19 FBA_D20 FBA_D21 FBA_D22 FBA_D23 FBA_D24 FBA_D25 FBA_D26 FBA_D27 FBA_D28 FBA_D29 FBA_D30 FBA_D31
net group VRAM_EDC_45R: nets FBA_EDC0 FBA_EDC1 FBA_EDC2 FBA_EDC3
net group XDP-MW: nets XDP_PRDY# XDP_PREQ# XDP_TDI XDP_TDO_CPU XDP_TMS XDP_TRST#
net group XTAL-MW: nets HDMI_27MHZ_OUT MEC_XTAL1_R MEC_XTAL2 RTC_X1 RTC_X2 XTAL24_IN XTAL24_IN_R XTAL24_IN_R_U42 XTAL24_IN_U42 XTAL24_OUT XTAL24_OUT_R XTAL24_OUT_R_U42 XTAL24_OUT_U42 XTLI_HDMI XTLO_HDMI
net group XTAL_27-MW: nets 27MHZ_OUT_R

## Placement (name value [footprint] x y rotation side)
AFTP2601  AFTE14P-GP  [AFTE14P-75]  207.54 68.67 0 top
AFTP2602  AFTE14P-GP  [AFTE14P-75]  207.54 70.57 0 top
AFTP2603  AFTE14P-GP  [AFTE14P-75]  202.71 68.79 0 top
AFTP2604  AFTE14P-GP  [AFTE14P-75]  204.62 68.79 0 top
AFTP2901  AFTE14P-GP  [AFTE14P-75]  36.75 6.95 45 top
AFTP2902  AFTE14P-GP  [AFTE14P-75]  36.85 3.01 45 top
AFTP2903  AFTE14P-GP  [AFTE14P-75]  31.9 11.26 315 top
AFTP2904  AFTE14P-GP  [AFTE14P-75]  30.25 12.41 315 top
AFTP4301  AFTE14P-GP  [AFTE14P-75]  17.67 94.19 0 top
AFTP4302  AFTE14P-GP  [AFTE14P-75]  15.77 94.19 0 top
AFTP4303  AFTE14P-GP  [AFTE14P-75]  23.9 92.04 0 top
AFTP4304  AFTE14P-GP  [AFTE14P-75]  21.23 94.58 0 top
AFTP4305  AFTE14P-GP  [AFTE14P-75]  23.39 93.94 0 top
AFTP4306  AFTE14P-GP  [AFTE14P-75]  192.81 22.82 0 top
AFTP4307  AFTE14P-GP  [AFTE14P-75]  190.9 22.82 0 top
AFTP4308  AFTE14P-GP  [AFTE14P-75]  189 22.82 0 top
AFTP4309  AFTE14P-GP  [AFTE14P-75]  185.19 22.82 0 top
AFTP4310  AFTE14P-GP  [AFTE14P-75]  183.28 22.82 0 top
AFTP4311  AFTE14P-GP  [AFTE14P-75]  181.38 22.82 0 top
AFTP4312  AFTE14P-GP  [AFTE14P-75]  175.66 22.82 0 top
AFTP4313  AFTE14P-GP  [AFTE14P-75]  177.57 22.82 0 top
AFTP4314  AFTE14P-GP  [AFTE14P-75]  179.47 22.82 0 top
AFTP4315  AFTE14P-GP  [AFTE14P-75]  187.09 22.82 0 top
AFTP4316  AFTE14P-GP  [AFTE14P-75]  22.04 92.49 0 top
AFTP6301  AFTE14P-GP  [AFTE14P-75]  227.48 17.87 0 top
AFTP6303  AFTE14P-GP  [AFTE14P-75]  214.78 10.63 180 top
AFTP6304  AFTE14P-GP  [AFTE14P-75]  226.59 20.53 180 top
AFTP6529  AFTE14P-GP  [AFTE14P-75]  96.67 9.74 180 top
AFTP6530  AFTE14P-GP  [AFTE14P-75]  100.48 9.74 0 top
AFTP6531  AFTE14P-GP  [AFTE14P-75]  126.51 9.1 0 top
AFTP6532  AFTE14P-GP  [AFTE14P-75]  146.71 6.23 0 top
AFTP6533  AFTE14P-GP  [AFTE14P-75]  143.53 6.18 0 top
AFTP6534  AFTE14P-GP  [AFTE14P-75]  123.21 18.76 0 top
AFTP6535  AFTE14P-GP  [AFTE14P-75]  120.42 17.99 0 top
AFTP6536  AFTE14P-GP  [AFTE14P-75]  117.88 15.58 0 top
AFTP6537  AFTE14P-GP  [AFTE14P-75]  141.24 11.77 0 top
AFTP6540  AFTE14P-GP  [AFTE14P-75]  87.65 11.26 0 top
AFTP6541  AFTE14P-GP  [AFTE14P-75]  93.24 9.87 0 top
AFTP6542  AFTE14P-GP  [AFTE14P-75]  91.33 2.25 0 top
AFTP6543  AFTE14P-GP  [AFTE14P-75]  89.43 2.25 0 top
AFTP6544  AFTE14P-GP  [AFTE14P-75]  85.62 2.25 0 top
AFTP6545  AFTE14P-GP  [AFTE14P-75]  83.71 2.25 0 top
AFTP6546  AFTE14P-GP  [AFTE14P-75]  87.52 2.25 0 top
AFTP6547  AFTE14P-GP  [AFTE14P-75]  87.02 4.15 0 top
AFTP6548  AFTE14P-GP  [AFTE14P-75]  85.24 5.17 0 top
AFTP6549  AFTE14P-GP  [AFTE14P-75]  84.22 6.95 0 top
AFTP6550  AFTE14P-GP  [AFTE14P-75]  83.38 4.63 0 top
AFTP6551  AFTE14P-GP  [AFTE14P-75]  84.65 9.36 0 top
AFTP6552  AFTE14P-GP  [AFTE14P-75]  86.13 8.09 0 top
AFTP6553  AFTE14P-GP  [AFTE14P-75]  82.75 9.1 0 top
AFTP6554  AFTE14P-GP  [AFTE14P-75]  83.84 11.26 0 top
AFTP6555  AFTE14P-GP  [AFTE14P-75]  87.14 6.44 0 top
AFTP6556  AFTE14P-GP  [AFTE14P-75]  90.83 4.53 0 top
AFTP6557  AFTE14P-GP  [AFTE14P-75]  85.75 11.01 0 top
AFTP6558  AFTE14P-GP  [AFTE14P-75]  88.92 4.53 0 top
AFTP6559  AFTE14P-GP  [AFTE14P-75]  87.78 9.36 0 top
AFTP6560  AFTE14P-GP  [AFTE14P-75]  92.73 4.53 0 top
AFTP6561  AFTE14P-GP  [AFTE14P-75]  93.24 2.25 0 top
AFTP6562  AFTE14P-GP  [AFTE14P-75]  89.05 6.69 0 top
AFTP6563  AFTE14P-GP  [AFTE14P-75]  92.98 6.44 0 top
AFTP6564  AFTE14P-GP  [AFTE14P-75]  91.08 6.56 0 top
AFTP6565  AFTE14P-GP  [AFTE14P-75]  91.71 8.6 0 top
AFTP6566  AFTE14P-GP  [AFTE14P-75]  89.68 9.36 0 top
BATT1  HIG-CON10-2-GP  [A2014WRA-SF-10PNLNG1NS1R]  184.2 17.5 180 bottom
C715  SC10U6D3V3MX-GP  [C603H38]  115.08 57.49 0 top
C716  SC1U10V2KX-1GP  [C402H22]  135.4 42.2 180 bottom
C717  SC1U10V2KX-1GP  [C402H22]  127.15 49.24 270 top
C718  SCD1U25V2KX-1-DL-GP  [C402H22]  63.39 23.96 0 top
C719  SC1U10V2KX-1GP  [C402H22]  76.22 56.98 0 top
C720  SCD1U25V2KX-1-DL-GP  [C402H22]  126.39 48.08 180 top
C721  SCD1U25V2KX-1-DL-GP  [C402H22]  125.62 48.08 180 top
C1101  SC1U10V2KX-1GP  [C402H22]  114.57 54.37 90 top
C1102  SC1U10V2KX-1GP  [C402H22]  120.04 64.6 90 top
C1103  SC1U10V2KX-1GP  [C402H22]  122.07 64.73 270 top
C1104  SC1U10V2KX-1GP  [C402H22]  125.14 70.06 90 top
C1105  SC1U10V2KX-1GP  [C402H22]  125.14 70.83 90 top
C1106  SC1U10V2KX-1GP  [C402H22]  126.13 67.52 0 top
C1107  SC1U10V2KX-1GP  [C402H22]  119.91 82.51 0 bottom
C1108  SC1U10V2KX-1GP  [C402H22]  115.29 49.97 270 top
C1109  SC1U10V2KX-1GP  [C402H22]  117.52 51.85 180 top
C1110  SC1U10V2KX-1GP  [C402H22]  115.29 52.86 270 top
C1111  SC1U10V2KX-1GP  [C402H22]  115.31 50.78 270 top
C1112  SC22U6D3V3MX-1-GP  [C603H40]  126 34.35 90 top
C1113  SC22U6D3V3MX-1-GP  [C603H40]  117.11 44.03 180 top
C1114  SC1U10V2KX-1GP  [C402H22]  123.59 43.39 270 top
C1115  SC22U6D3V3MX-1-GP  [C603H40]  107.39 13.12 270 bottom
C1116  SC1U10V2KX-1GP  [C402H22]  118.64 45.09 90 top
C1117  SC1U10V2KX-1GP  [C402H22]  118.69 45.95 90 top
C1118  SC22U6D3V3MX-1-GP  [C603H40]  121.43 44.79 0 top
C1119  SC1U10V2KX-1GP  [C402H22]  122.45 43.78 0 top
C1120  SC10U6D3V3MX-GP  [C603H38]  103.27 15.84 270 bottom
C1121  SC1U10V2KX-1GP  [C402H22]  121.08 46.72 270 top
C1124  SC1U10V2KX-1GP  [C402H22]  143.89 52.28 270 top
C1125  SC1U10V2KX-1GP  [C402H22]  125.06 52.92 270 top
C1126  SC1U10V2KX-1GP  [C402H22]  143.89 51.52 270 top
C1127  SC1U10V2KX-1GP  [C402H22]  125.75 59.4 180 top
C1202  SC10U6D3V3MX-GP  [C603H38]  62.25 63.33 90 top
C1203  SC10U6D3V3MX-GP  [C603H38]  66.7 62.06 180 top
C1204  SC10U6D3V3MX-GP  [C603H38]  61.48 54.29 270 top
C1205  SC10U6D3V3MX-GP  [C603H38]  71.14 53.94 180 top
C1206  SC10U6D3V3MX-GP  [C603H38]  68.22 59.14 180 top
C1207  SC1U10V2KX-1GP  [C402H22]  69.74 18.38 90 top
C1208  SC10U6D3V3MX-GP  [C603H38]  71.78 49.24 0 top
C1209  SC10U6D3V3MX-GP  [C603H38]  69.49 40.85 0 top
C1210  SC10U6D3V3MX-GP  [C603H38]  69.74 68.67 270 top
C1211  SC4D7U6D3V2MX-1-GP  [C402H22]  67.84 21.17 180 top
C1212  SC4D7U6D3V2MX-1-GP  [C402H22]  68.6 21.17 180 top
C1213  SC1U10V2KX-L1-GP  [C402H22]  69.74 19.14 90 top
C1214  SC1U10V2KX-1GP  [C402H22]  69.36 77.81 270 top
C1215  SC1U10V2KX-1GP  [C402H22]  59.96 71.97 270 top
C1216  SC1U10V2KX-1GP  [C402H22]  62.12 83.4 90 top
C1217  SC1U10V2KX-1GP  [C402H22]  62.12 39.71 90 top
C1218  SC1U10V2KX-1GP  [C402H22]  62 28.79 90 top
C1219  SC1U10V2KX-1GP  [C402H22]  70.44 55.54 90 top
C1220  SC1U10V2KX-1GP  [C402H22]  69.36 36.28 270 top
C1221  SC1U10V2KX-1GP  [C402H22]  70.51 23.96 0 top
C1222  SCD022U16V2KX-3GP  [C402H22]  70.25 47.71 270 top
C1223  SC4D7U6D3V2MX-1-GP  [C402H22]  62 21.04 180 top
C1224  SC4D7U6D3V2MX-1-GP  [C402H22]  61.11 19.26 0 top
C1225  SC1U10V2KX-1GP  [C402H22]  61.87 19.26 0 top
C1226  SC1U10V2KX-1GP  [C402H22]  62.63 19.26 0 top
C1227  SC4D7U6D3V2MX-1-GP  [C402H22]  61.23 21.04 180 top
C1228  SCD1U16V2KX-L-GP  [C402H22]  66.7 21.55 90 top
C1229  SCD1U25V2KX-1-DL-GP  [C402H22]  70.25 46.19 90 top
C1230  SC4D7U6D3V2MX-1-GP  [C402H22]  49.04 21.17 180 top
C1231  SC4D7U6D3V2MX-1-GP  [C402H22]  56.79 18.63 90 top
C1232  SC4D7U6D3V2MX-1-GP  [C402H22]  69.74 19.9 90 top
C1301  SCD1U25V2KX-1-DL-GP  [C402H22]  48.53 41.62 270 top
C1303  SC10U6D3V3MX-GP  [C603H38]  52.34 64.1 180 top
C1304  SC10U6D3V3MX-GP  [C603H38]  56.54 41.29 270 top
C1305  SC10U6D3V3MX-GP  [C603H38]  56.54 42.63 270 top
C1306  SC10U6D3V3MX-GP  [C603H38]  56.51 53.99 90 top
C1307  SC10U6D3V3MX-GP  [C603H38]  56.48 55.33 90 top
C1308  SC10U6D3V3MX-GP  [C603H38]  48.03 45.05 270 top
C1309  SC10U6D3V3MX-GP  [C603H38]  48.08 52.11 270 top
C1310  SC10U6D3V3MX-GP  [C603H38]  48.05 56.65 270 top
C1311  SC4D7U6D3V2MX-1-GP  [C402H22]  56.79 19.39 90 top
C1312  SC4D7U6D3V2MX-1-GP  [C402H22]  55.65 21.3 180 top
C1313  SC1U10V2KX-1GP  [C402H22]  56.79 20.18 90 top
C1314  SC1U10V2KX-L1-GP  [C402H22]  56.41 21.3 180 top
C1315  SC1U10V2KX-1GP  [C402H22]  51.07 63.46 180 top
C1316  SC1U10V2KX-1GP  [C402H22]  49.42 36.41 0 top
C1317  SC1U10V2KX-1GP  [C402H22]  49.42 29.42 0 top
C1318  SC1U10V2KX-1GP  [C402H22]  54.22 32.32 90 top
C1319  SC1U10V2KX-1GP  [C402H22]  49.3 73.11 0 top
C1320  SC1U10V2KX-1GP  [C402H22]  59.08 69.18 180 top
C1321  SC1U10V2KX-1GP  [C402H22]  56.54 79.34 270 top
C1322  SC1U10V2KX-1GP  [C402H22]  49.17 83.27 90 top
C1323  SCD022U16V2KX-3GP  [C402H22]  48.53 43.27 90 top
C1324  SC10U6D3V3MX-GP  [C603H38]  45.74 20.53 270 top
C1325  SC10U6D3V3MX-GP  [C603H38]  45.74 19.26 270 top
C1326  SC1U10V2KX-1GP  [C402H22]  48.2 21.14 180 top
C1327  SC1U10V2KX-1GP  [C402H22]  47.37 21.14 180 top
C1328  SCD1U16V2KX-L-GP  [C402H22]  53.72 21.63 90 top
C1329  SC2D2U10V3KX-L-GP  [C603H36]  54.63 23.84 0 top
C1330  SC4D7U6D3V2MX-1-GP  [C402H22]  54.88 21.3 180 top
C1331  SC4D7U6D3V2MX-1-GP  [C402H22]  69.74 20.66 90 top
C1601  SCD1U25V2KX-1-DL-GP  [C402H22]  209.77 41.31 90 top
C1602  SCD1U25V2KX-1-DL-GP  [C402H22]  209.77 42.07 90 top
C1605  SCD22U10V2KX-1GP  [C402H22]  147.91 77.06 180 bottom
C1606  SCD22U10V2KX-1GP  [C402H22]  147.15 77.06 180 bottom
C1607  SCD22U10V2KX-1GP  [C402H22]  147.85 79.46 90 bottom
C1608  SCD22U10V2KX-1GP  [C402H22]  147.85 80.22 90 bottom
C1609  SCD22U10V2KX-1GP  [C402H22]  147.85 80.99 90 bottom
C1610  SCD22U10V2KX-1GP  [C402H22]  147.85 81.75 90 bottom
C1611  SCD22U10V2KX-1GP  [C402H22]  147.85 82.51 90 bottom
C1612  SCD22U10V2KX-1GP  [C402H22]  147.85 83.27 90 bottom
C1613  SCD1U25V2KX-1-DL-GP  [C402H22]  209.77 40.52 90 top
C1614  SCD1U25V2KX-1-DL-GP  [C402H22]  209.77 39.76 90 top
C1701  SC220P50V2KX-3GP  [C402H22]  117.88 18.12 270 bottom
C1704  SC10U6D3V3MX-GP  [C603H38]  103.27 17.11 270 bottom
C1710  SCD47U10V2KX-GP  [C402H22]  91.28 11.31 270 top
C1711  SCD01U50V2KX-1GP  [C402H22]  124.48 84.16 0 bottom
C1801  SC15P50V2JN-2-GP  [C402H22]  136.1 57.31 180 bottom
C1802  SC12P50V2JN-3GP  [C402H24]  136.06 53.94 0 bottom
C1803  SC10P50V2JN-4DLGP  [C402H22]  103.4 18.88 270 bottom
C1804  SC10P50V2JN-4DLGP  [C402H22]  103.4 19.65 270 bottom
C1805  SC1U10V2KX-1GP  [C402H22]  73.3 20.61 0 top
C1806  SC1U10V2KX-1GP  [C402H22]  70.96 22.57 270 top
C2101  SC1U10V2KX-1GP  [C402H22]  139.97 40.6 270 bottom
C2102  SC1U10V2KX-1GP  [C402H22]  97.56 22.53 90 bottom
C2103  SC1U10V2KX-1GP  [C402H22]  115.34 33.87 90 top
C2104  SC1U10V2KX-1GP  [C402H22]  114.98 47.91 180 top
C2105  SC1U10V2KX-1GP  [C402H22]  115.56 44.92 270 top
C2106  SC1U10V2KX-1GP  [C402H22]  115.56 45.68 270 top
C2107  SC1U10V2KX-1GP  [C402H22]  119.02 41.85 90 top
C2108  SC1U10V2KX-1GP  [C402H22]  118.33 33.87 270 top
C2109  SC1U10V2KX-1GP  [C402H22]  115.69 44.13 90 top
C2110  SCD1U25V2KX-1-DL-GP  [C402H22]  119.07 43.79 180 top
C2111  SCD1U25V2KX-1-DL-GP  [C402H22]  118.23 43.79 180 top
C2112  SCD1U25V2KX-1-DL-GP  [C402H22]  94.89 36.16 180 top
C2113  SC22U6D3V3MX-1-GP  [C603H40]  126.28 35.64 90 top
C2114  SC22U6D3V3MX-1-GP  [C603H40]  120.11 44.07 180 top
C2115  SC22U6D3V3MX-1-GP  [C603H40]  140.13 35.39 90 bottom
C2116  SC1U10V2KX-1GP  [C402H22]  115.29 49.15 270 top
C2117  SC1U10V2KX-1GP  [C402H22]  114.57 46.44 90 top
C2118  SCD1U25V2KX-1-DL-GP  [C402H22]  116.99 48.22 90 top
C2119  SC22U6D3V3MX-1-GP  [C603H40]  124 48.04 180 top
C2120  SC1U10V2KX-1GP  [C402H22]  97.56 21.72 90 bottom
C2121  SC1U10V2KX-1GP  [C402H22]  118.77 46.82 270 top
C2122  SC22U6D3V3MX-1-GP  [C603H40]  142.51 35.39 270 bottom
C2201  SC12P50V2JN-3GP  [C402H24]  139.21 28.03 0 bottom
C2202  SC15P50V2JN-2-GP  [C402H22]  139.21 31.33 180 bottom
C2405  SC100P50V2JN-3GP  [C402H22]  144.75 4.99 180 top
C2406  SCD1U25V2KX-1-DL-GP  [C402H22]  140.1 9.49 180 bottom
C2407  SCD1U25V2KX-1-DL-GP  [C402H22]  146.83 4.53 180 top
C2408  SCD1U25V2KX-1-DL-GP  [C402H22]  149.88 2.12 0 top
C2409  SCD01U50V2KX-1DLGP  [C402H22]  161.44 21.55 180 top
C2410  SCD1U25V2KX-1-DL-GP  [C402H22]  161.82 16.47 90 top
C2411  SCD1U25V2KX-1-DL-GP  [C402H22]  140.99 13.68 90 bottom
C2412  SCD1U25V2KX-1-DL-GP  [C402H22]  140.23 24.47 0 bottom
C2413  SCD1U25V2KX-1-DL-GP  [C402H22]  145.51 4.99 180 top
C2414  SCD1U25V2KX-1-DL-GP  [C402H22]  152.04 23.71 180 bottom
C2416  SCD1U25V2KX-1-DL-GP  [C402H22]  151.91 15.45 270 bottom
C2418  SC1U10V2KX-1GP  [C402H22]  161.82 15.71 90 top
C2420  SCD1U25V2KX-1-DL-GP  [C402H22]  151.91 4.53 0 top
C2421  SCD1U25V2KX-1-DL-GP  [C402H22]  151.91 16.98 270 bottom
C2422  SCD1U25V2KX-1-DL-GP  [C402H22]  146.58 3.26 90 top
C2423  SCD1U25V2KX-1-DL-GP  [C402H22]  148.48 26.38 180 top
C2424  SC10P50V2JN-4GP  [C402H22]  157.75 4.91 90 top
C2425  SC10P50V2JN-4GP  [C402H22]  156.23 4.91 270 top
C2426  SC2D2U10V2KX-GP  [C402H22]  160.93 5.8 90 top
C2428  SCD1U25V2KX-1-DL-GP  [C402H22]  160.42 2.75 0 top
C2429  SCD1U25V2KX-1-DL-GP  [C402H22]  161.82 17.99 90 top
C2430  SC2200P50V2KX-2GP  [C402H22]  149.5 4.02 270 top
C2431  SC2200P50V2KX-2GP  [C402H22]  149.5 5.29 180 bottom
C2435  SC2200P50V2KX-2GP  [C402H22]  147.59 4.53 0 top
C2501  SC10U10V5KX-2GP  [C805H54]  171.98 15.07 0 bottom
C2502  SCD1U16V2KX-3GP  [C402H22]  172.36 12.03 270 bottom
C2503  SCD47U10V2KX-1-GP  [C402H22]  168.68 2.75 90 top
C2601  SC10U6D3V3MX-GP  [C603H38]  49.55 17.36 90 top
C2602  SCD1U25V2KX-1-DL-GP  [C402H22]  45.99 15.96 270 top
C2603  SC2200P50V2KX-2GP  [C402H22]  203.98 71.59 270 top
C2604  SC4D7U6D3V3KX-GP  [C603H36]  203.91 72.6 270 top
C2605  SCD1U25V2KX-1-DL-GP  [C402H22]  203.98 70.83 270 top
C2606  SC470P50V3JN-2GP  [C603H36]  169.69 43.01 180 bottom
C2607  SC2200P50V2KX-2GP  [C402H22]  45.36 14.69 0 top
C2608  SCD1U16V2KX-3GP  [C402H22]  52.98 16.98 270 top
C2609  SCD1U16V2KX-3GP  [C402H22]  53.74 14.69 90 top
C2610  SCD1U16V2KX-3GP  [C402H22]  43.45 9.23 90 top
C2612  SCD1U25V2KX-1-DL-GP  [C402H22]  141.88 76.41 180 top
C2613  SC100P50V2JN-3DLGP  [C402H22]  144.17 75.91 180 top
C2614  SCD1U16V2KX-3GP  [C402H22]  43.81 8.09 180 top
C2714  SC1U10V2KX-1GP  [C402H22]  22.88 31.96 180 top
C2721  SCD1U16V2KX-3GP  [C402H22]  26.56 30.19 90 top
C2722  SCD1U25V2KX-1-DL-GP  [C402H22]  21.99 29.81 270 top
C2726  SCD1U25V2KX-1-DL-GP  [C402H22]  15.01 14.69 90 top
C2727  SC10U6D3V3MX-DL-GP  [C603H36]  20.9 9.49 0 top
C2729  SCD1U25V2KX-1-DL-GP  [C402H22]  30.25 15.05 180 top
C2730  SC10U6D3V3MX-DL-GP  [C603H36]  22.63 22.57 270 top
C2731  SC10U6D3V3MX-DL-GP  [C603H36]  21.18 9.36 0 bottom
C2732  SC10U6D3V3MX-DL-GP  [C603H36]  24.33 9.79 270 bottom
C2733  SC10U6D3V3MX-DL-GP  [C603H36]  26.36 12.25 270 bottom
C2734  SC10U6D3V3MX-DL-GP  [C603H36]  22.75 20.41 90 top
C2735  SC10U6D3V3MX-DL-GP  [C603H36]  21.1 13.42 180 bottom
C2736  SC10U6D3V3MX-DL-GP  [C603H36]  26.18 21.42 180 top
C2737  SC2D2U10V3KX-1DLGP-U  [C603H36]  19.58 9.49 180 top
C2738  SC10P50V2JN-4DLGP  [C402H22]  30.88 17.16 270 top
C2739  SC1U50V3KX-1-GP  [C603H36]  20.72 21.17 0 top
C2740  SCD1U25V2KX-1-DL-GP  [C402H22]  23.64 21.55 270 top
C2741  SC1U50V3KX-1-GP  [C603H36]  19.07 21.17 180 top
C2742  SCD1U25V2KX-1-DL-GP  [C402H22]  24.4 10.88 270 bottom
C2743  SC10U6D3V3MX-DL-GP  [C603H36]  31.39 15.45 180 top
C2744  SCD1U25V2KX-1-DL-GP  [C402H22]  21.61 22.47 0 bottom
C2745  SC10U6D3V3MX-DL-GP  [C603H36]  17.93 22.44 0 bottom
C2746  SCD1U16V2KX-3DLGP  [C402H22]  27.45 13.3 90 bottom
C2747  SCD1U25V2KX-1-DL-GP  [C402H22]  29.46 15.05 180 top
C2748  SCD1U25V2KX-1-DL-GP  [C402H22]  26.69 11.14 270 bottom
C2749  SCD1U25V2KX-1-DL-GP  [C402H22]  21.94 9.89 0 top
C2907  SC10U6D3V3MX-DL-GP  [C603H36]  19.9 9.37 180 bottom
C2908  SC10U6D3V3MX-DL-GP  [C603H36]  14.63 10.88 90 bottom
C3401  SC1U10V2KX-1GP  [C402H22]  21.23 46.95 90 bottom
C3402  SCD1U25V2KX-1-DL-GP  [C402H22]  23.13 40.98 0 top
C3403  SCD1U25V2KX-1-DL-GP  [C402H22]  21.23 46.19 90 bottom
C3404  SC22U6D3V3MX-1-GP  [C603H40]  20.21 53.17 0 bottom
C3405  SC22U6D3V3MX-1-GP  [C603H40]  21.48 53.17 0 bottom
C3502  SC1U25V2KX-4-GP  [C402H22]  21.76 38.29 0 bottom
C3503  SCD1U16V2KX-3GP  [C402H22]  21.76 34.35 0 bottom
C3507  SCD1U25V2KX-1-DL-GP  [C402H22]  17.29 37.81 0 bottom
C3508  SC1U10V2KX-1GP  [C402H22]  16.1 34.5 0 bottom
C3512  SC22U6D3V5MX-2GP  [C805H58]  13.48 35.65 90 bottom
C3513  SC10U6D3V3MX-GP  [C603H38]  16.28 37.81 0 bottom
C3514  SC10U6D3V3MX-GP  [C603H38]  17.11 34.48 0 bottom
C3515  SCD1U16V2KX-3GP  [C402H22]  20.72 28.15 90 bottom
C3516  SC1U10V2KX-1GP  [C402H22]  20.72 28.92 90 bottom
C3517  SC1U10V2KX-1GP  [C402H22]  18.77 31.15 180 top
C3518  SCD1U25V2KX-1-DL-GP  [C402H22]  18 31.15 180 top
C3519  SC22U6D3V3MX-1-GP  [C603H40]  17.17 31.2 0 bottom
C3520  SC22U6D3V3MX-1-GP  [C603H40]  17.17 28.79 180 bottom
C3601  SCD1U25V2KX-1-DL-GP  [C402H22]  22.75 50.51 270 top
C3602  SCD1U25V2KX-1-DL-GP  [C402H22]  22.75 51.27 270 top
C3603  SCD1U25V2KX-1-DL-GP  [C402H22]  25.55 26.73 180 top
C3604  SCD1U25V2KX-1-DL-GP  [C402H22]  26.36 26.73 180 top
C3701  SCD1U25V2KX-1-DL-GP  [C402H22]  39.01 23.46 90 top
C3702  SCD1U25V2KX-1-DL-GP  [C402H22]  39.01 24.98 90 top
C3703  SC1U10V2KX-1GP  [C402H22]  39.01 24.22 90 top
C3704  SC1U10V2KX-1GP  [C402H22]  29.1 36.16 180 top
C3705  SCD1U25V2KX-1-DL-GP  [C402H22]  28.34 36.16 180 top
C3707  SC1U50V3KX-GP  [C603H32]  39.44 32.57 90 top
C3709  SCD1U25V2KX-1-DL-GP  [C402H22]  42.57 34.5 180 top
C3710  SC2D2U10V3KX-1GP  [C603H36]  41.47 34.61 180 top
C3711  SC390P50V2KX-GP-U  [C402H24]  10.18 89.5 0 top
C3712  SC390P50V2KX-GP-U  [C402H24]  12.21 90.13 180 top
C3715  SC1U10V2KX-1GP  [C402H22]  41.17 27.14 90 top
C3716  SCD1U25V2KX-1-DL-GP  [C402H22]  29.48 33.23 270 top
C3717  SCD1U25V2KX-1-DL-GP  [C402H22]  29.48 30.19 90 top
C3718  SC10U6D3V3MX-GP  [C603H38]  28.09 34.12 0 top
C3719  SCD1U25V2KX-1-DL-GP  [C402H22]  27.58 36.16 180 top
C3720  SCD22U10V2KX-1GP  [C402H22]  41.8 28.28 180 top
C3721  SCD1U25V2KX-1-DL-GP  [C402H22]  41.04 25.23 90 top
C3722  SC1U10V2KX-1GP  [C402H22]  41.04 26 90 top
C3723  SCD1U25V2KX-1-DL-GP  [C402H22]  41.04 24.47 90 top
C3801  SCD1U25V2KX-1-DL-GP  [C402H22]  37.49 64.35 0 top
C3802  SCD1U25V2KX-1-DL-GP  [C402H22]  36.72 64.35 0 top
C3803  SCD1U25V2KX-1-DL-GP  [C402H22]  38.76 50.51 180 top
C3804  SCD1U25V2KX-1-DL-GP  [C402H22]  37.99 50.51 180 top
C3805  SCD1U25V2KX-1-DL-GP  [C402H22]  36.72 50.38 180 top
C3806  SCD1U25V2KX-1-DL-GP  [C402H22]  35.96 50.38 180 top
C3807  SCD1U25V2KX-1-DL-GP  [C402H22]  42.57 54.57 270 top
C3808  SCD1U25V2KX-1-DL-GP  [C402H22]  42.57 57.62 270 top
C3809  SCD1U25V2KX-1-DL-GP  [C402H22]  42.57 56.86 270 top
C3810  SCD1U25V2KX-1-DL-GP  [C402H22]  42.82 61.05 270 top
C3811  SCD1U25V2KX-1-DL-GP  [C402H22]  42.82 60.29 270 top
C3812  SCD1U25V2KX-1-DL-GP  [C402H22]  39.9 52.03 180 top
C3813  SCD1U25V2KX-1-DL-GP  [C402H22]  40.66 52.03 180 top
C3814  SCD1U25V2KX-1-DL-GP  [C402H22]  42.57 53.81 270 top
C3815  SCD1U25V2KX-1-DL-GP  [C402H22]  40.28 59.9 180 top
C3816  SCD1U25V2KX-1-DL-GP  [C402H22]  33.8 60.92 270 top
C3817  SCD1U25V2KX-1-DL-GP  [C402H22]  39.52 59.9 180 top
C3818  SCD1U25V2KX-1-DL-GP  [C402H22]  37.36 52.54 0 top
C3819  SC10U6D3V3MX-GP  [C603H38]  33.68 61.94 270 top
C3821  SCD1U25V2KX-GP  [C402H22]  29.36 89.88 270 top
C3861  SCD1U25V2KX-1-DL-GP  [C402H22]  16.66 85.81 180 top
C3862  SCD1U25V2KX-1-DL-GP  [C402H22]  15.9 85.81 180 top
C3863  SCD1U25V2KX-1-DL-GP  [C402H22]  10.43 88.61 0 bottom
C3864  SCD1U25V2KX-1-DL-GP  [C402H22]  9.67 88.61 0 bottom
C3865  SCD1U25V2KX-1-DL-GP  [C402H22]  34.82 45.81 180 top
C4001  SC470P50V2KX-3GP  [C402H22]  198.01 46.19 270 top
C4002  SC470P50V2KX-3GP  [C402H22]  199.54 46.19 90 top
C4003  SCD22U10V2KX-1GP  [C402H22]  203.22 50.76 0 top
C4004  SC10U25V5KX-DL-GP  [C805H58]  198.39 42.38 180 bottom
C4005  SC10U25V5KX-DL-GP  [C805H58]  200.2 42.38 180 bottom
C4006  SC10U6D3V3MX-GP  [C603H38]  72.03 4.66 270 top
C4007  SCD1U25V2KX-1-DL-GP  [C402H22]  75.84 9.49 90 top
C4009  SC10U6D3V3MX-GP  [C603H38]  164.36 5.29 270 top
C4012  SC10U6D3V3MX-GP  [C603H38]  113.56 8.72 270 bottom
C4013  SC10U6D3V3MX-GP  [C603H38]  107.46 11.29 0 bottom
C4017  SCD1U16V2KX-3GP  [C402H22]  112.54 13.93 0 bottom
C4031  SC1U10V2KX-1GP  [C402H22]  80.79 4.14 90 top
C4032  SC1U10V2KX-1GP  [C402H22]  80.79 4.9 90 top
C4033  SCD1U25V2KX-1-DL-GP  [C402H22]  77.46 7.43 180 top
C4034  SC1U10V2KX-1GP  [C402H22]  109.49 11.52 90 bottom
C4035  SC22U6D3V3MX-1-GP  [C603H40]  72.03 3.39 270 top
C4036  SC22U6D3V3MX-1-GP  [C603H40]  72.03 2.12 270 top
C5501  SCD1U25V2KX-1-DL-GP  [C402H22]  103.3 101.03 90 top
C5502  SC4D7U6D3V3KX-GP  [C603H36]  98.22 88.25 180 bottom
C5503  SC4D7U6D3V3KX-GP  [C603H36]  109.11 91.65 180 bottom
C5504  SCD1U25V2KX-1-DL-GP  [C402H22]  103.3 100.27 90 top
C5505  SC4D7U6D3V3KX-GP  [C603H36]  105.56 91.78 180 bottom
C5506  SCD1U25V2KX-1-DL-GP  [C402H22]  103.3 99.45 90 top
C5507  SCD1U25V2KX-1-DL-GP  [C402H22]  104.41 91.78 180 bottom
C5508  SC1U10V2KX-1GP  [C402H22]  103.65 91.78 0 bottom
C5509  SCD1U25V2KX-1-DL-GP  [C402H22]  103.3 98.69 90 top
C5510  SCD1U25V2KX-1-DL-GP  [C402H22]  87.34 101.62 270 top
C5511  SCD1U25V2KX-1-DL-GP  [C402H22]  87.34 102.39 270 top
C5512  SCD1U50V3KX-GP  [C603H36]  90.69 99.53 180 top
C5513  SC1KP50V2KX-1DLGP  [C402H22]  91.71 99.4 180 top
C5514  SC4D7U25V5KX-DL-GP  [C805H54]  83.84 99.4 0 bottom
C5515  SC4D7U6D3V3KX-GP  [C603H36]  69.49 101.31 180 top
C5516  SCD1U50V3KX-GP  [C603H36]  81.17 99.15 90 top
C5517  SC10U25V5KX-DL-GP  [C805H58]  79.27 92.8 180 bottom
C5519  SCD1U25V2KX-1-DL-GP  [C402H22]  99.72 101.56 90 top
C5531  SCD1U25V2KX-1-DL-GP  [C402H22]  93.49 102.83 270 top
C5532  SCD1U25V2KX-1-DL-GP  [C402H22]  93.49 102.07 270 top
C5533  SCD1U25V2KX-1-DL-GP  [C402H22]  99.72 102.32 90 top
C5534  SC1KP50V2KX-1DLGP  [C402H22]  114.19 99.91 270 top
C5535  SC10U10V5KX-2GP  [C805H54]  62.89 91.78 90 bottom
C5536  SC10U10V5KX-2GP  [C805H54]  62.89 93.69 90 bottom
C5537  SC10U10V5KX-2GP  [C805H54]  77.46 92.8 180 bottom
C5542  SCD1U50V3KX-GP  [C603H36]  115.46 98.89 270 top
C5724  SCD75P50V1CN-GP  [C0201H13]  20.09 73.11 180 top
C5725  SC1U10V2KX-1GP  [C402H22]  24.66 63.08 270 top
C5726  SCD1U25V2KX-1-DL-GP  [C402H22]  21.76 76.21 0 bottom
C5727  SCD1U25V2KX-1-DL-GP  [C402H22]  31.26 71.37 270 top
C5728  SCD1U25V2KX-1-DL-GP  [C402H22]  31.26 70.61 270 top
C5729  SC18P50V2JN-1-GP  [C402H22]  19.32 62.06 0 top
C5730  SC18P50V2JN-1-GP  [C402H22]  19.32 64.86 180 top
C5731  SCD1U25V2KX-1-DL-GP  [C402H22]  32.79 68.55 270 top
C5732  SCD1U25V2KX-1-DL-GP  [C402H22]  31.26 69.01 270 top
C5733  SCD1U25V2KX-1-DL-GP  [C402H22]  31.26 72.97 270 top
C5734  SCD1U25V2KX-1-DL-GP  [C402H22]  31.26 69.77 270 top
C5735  SCD1U25V2KX-1-DL-GP  [C402H22]  31.26 72.21 270 top
C5736  SCD1U25V2KX-1-DL-GP  [C402H22]  16.02 80.61 180 top
C5737  SCD1U25V2KX-1-DL-GP  [C402H22]  32.79 67.78 270 top
C5738  SCD1U25V2KX-1-DL-GP  [C402H22]  41.8 67.02 270 top
C5739  SCD1U25V2KX-1-DL-GP  [C402H22]  41.8 66.25 270 top
C5740  SCD1U25V2KX-1-DL-GP  [C402H22]  39.52 67.02 270 top
C5741  SCD1U25V2KX-1-DL-GP  [C402H22]  39.52 66.25 270 top
C5824  SCD1U25V2KX-1-DL-GP  [C402H22]  19.71 72.1 0 bottom
C5825  SCD1U25V2KX-1-DL-GP  [C402H22]  18.94 72.1 0 bottom
C5826  SCD1U25V2KX-1-DL-GP  [C402H22]  18.18 72.1 0 bottom
C5827  SCD47U10V2KX-1-GP  [C402H22]  30.8 75.78 180 top
C5828  SCD1U25V2KX-1-DL-GP  [C402H22]  16.15 70.06 270 bottom
C5829  SCD1U25V2KX-1-DL-GP  [C402H22]  16.15 69.3 270 bottom
C5831  SCD47U10V2KX-1-GP  [C402H22]  26.18 63.08 270 top
C5832  SCD01U50V2KX-1DLGP  [C402H22]  20.26 68.34 180 bottom
C5833  SCD01U50V2KX-1DLGP  [C402H22]  16.15 68.54 90 bottom
C5834  SCD1U25V2KX-1-DL-GP  [C402H22]  20.85 71.33 270 bottom
C5836  SCD47U10V2KX-1-GP  [C402H22]  31.26 63.08 270 top
C5837  SCD01U50V2KX-1DLGP  [C402H22]  20.85 70.57 90 bottom
C5838  SCD1U25V2KX-1-DL-GP  [C402H22]  19.45 67.42 180 bottom
C5839  SCD1U25V2KX-1-DL-GP  [C402H22]  16.4 67.42 180 bottom
C5840  SCD47U10V2KX-1-GP  [C402H22]  28.72 63.08 270 top
C5841  SCD01U50V2KX-1DLGP  [C402H22]  17.17 67.42 0 bottom
C5842  SCD01U50V2KX-1DLGP  [C402H22]  17.93 67.42 0 bottom
C5843  SC10U6D3V3MX-GP  [C603H38]  28.21 64.73 0 top
C5844  SC10U6D3V3MX-GP  [C603H38]  33.29 64.73 0 top
C5845  SC10U6D3V3MX-GP  [C603H38]  30.75 64.73 0 top
C5846  SCD1U25V2KX-1-DL-GP  [C402H22]  15.64 67.42 180 bottom
C5847  SCD01U50V2KX-1DLGP  [C402H22]  18.69 67.42 0 bottom
C5848  SCD1U25V2KX-1-DL-GP  [C402H22]  17.39 70.22 180 bottom
C5849  SCD1U25V2KX-1-DL-GP  [C402H22]  19.71 70.22 180 bottom
C5850  SCD47U10V2KX-1-GP  [C402H22]  33.8 63.08 270 top
C5851  SCD01U50V2KX-1DLGP  [C402H22]  18.16 70.22 0 bottom
C5852  SCD01U50V2KX-1DLGP  [C402H22]  18.94 70.22 0 bottom
C5853  SC10U6D3V3MX-GP  [C603H38]  25.67 64.73 0 top
C5855  SC10U6D3V3MX-GP  [C603H38]  29.2 76.31 90 top
C5856  SC1U10V2KX-L1-GP  [C402H22]  15.77 58.25 0 bottom
C5857  SC10U6D3V3MX-L-GP  [C603H38]  18.94 54.44 180 bottom
C5858  SCD1U25V2KX-1-DL-GP  [C402H22]  20.59 54.82 90 bottom
C5859  SC68P50V2JN-1GP  [C402H22]  19.4 64.96 180 bottom
C5860  SC10U6D3V3MX-L-GP  [C603H38]  16.28 64.1 90 bottom
C5861  SC10U6D3V3MX-L-GP  [C603H38]  16.28 65.37 90 bottom
C6001  SCD01U50V2KX-1DLGP  [C402H22]  206.27 10.12 270 bottom
C6002  SCD1U25V2KX-1-DL-GP  [C402H22]  230.4 4.66 90 top
C6003  SCD01U50V2KX-1DLGP  [C402H22]  206.27 10.88 270 bottom
C6004  SC10U25V5KX-DL-GP  [C805H58]  213.38 11.01 180 bottom
C6005  SCD01U50V2KX-1DLGP  [C402H22]  206.27 8.6 270 bottom
C6006  SCD01U50V2KX-1DLGP  [C402H22]  206.27 9.36 270 bottom
C6302  SCD22U10V2KX-1GP  [C402H22]  208.14 16.79 90 bottom
C6303  SCD22U10V2KX-1GP  [C402H22]  208.14 17.55 90 bottom
C6304  SC33P50V2JN-3GP  [C402H22]  229.38 23.07 90 top
C6305  SC33P50V2JN-3GP  [C402H22]  229.38 21.55 90 top
C6306  SCD047U25V2KX-GP  [C402H22]  229.89 11.9 90 top
C6307  SCD1U25V2KX-1-DL-GP  [C402H22]  229.38 22.31 90 top
C6308  SCD047U25V2KX-GP  [C402H22]  229.38 20.79 90 top
C6311  SCD22U10V2KX-1GP  [C402H22]  211.13 18.52 90 bottom
C6312  SCD22U10V2KX-1GP  [C402H22]  211.13 19.28 90 bottom
C6313  SCD22U10V2KX-1GP  [C402H22]  211.13 21.52 90 bottom
C6314  SCD22U10V2KX-1GP  [C402H22]  211.13 22.28 90 bottom
C6315  SCD22U10V2KX-1GP  [C402H22]  211.13 24.52 90 bottom
C6316  SCD22U10V2KX-1GP  [C402H22]  211.13 25.28 90 bottom
C6317  SC22U6D3V3MX-1-GP  [C603H40]  229.89 10.88 90 top
C6318  SC22U6D3V3MX-1-GP  [C603H40]  229.64 19.77 90 top
C6501  SCD1U25V2KX-1-DL-GP  [C402H22]  97.2 15.56 0 bottom
C6502  SCD1U25V2KX-1-DL-GP  [C402H22]  116.99 13.17 270 bottom
C6504  SCD1U16V2KX-3GP  [C402H22]  95.78 15.2 270 bottom
C6505  SCD1U25V2KX-1-DL-GP  [C402H22]  155.6 8.22 90 bottom
C7003  SCD1U25V2KX-1-DL-GP  [C402H22]  207.03 59.96 270 top
C7004  SC10U6D3V3MX-GP  [C603H38]  208.43 61.17 180 top
C7301  SCD22U10V2KX-1GP  [C402H22]  145.18 77.05 0 bottom
C7302  SCD22U10V2KX-1GP  [C402H22]  145.94 77.05 0 bottom
C7303  SCD22U10V2KX-1GP  [C402H22]  143.91 80.25 270 bottom
C7304  SCD22U10V2KX-1GP  [C402H22]  143.91 79.46 270 bottom
C7305  SCD22U10V2KX-1GP  [C402H22]  143.53 81.37 270 bottom
C7306  SCD22U10V2KX-1GP  [C402H22]  143.53 82.13 270 bottom
C7307  SCD22U10V2KX-1GP  [C402H22]  144.42 83.4 270 bottom
C7308  SCD22U10V2KX-1GP  [C402H22]  143.78 84.16 270 bottom
C7310  SC4D7U6D3V3KX-GP  [C603H36]  145.82 120.36 270 bottom
C7312  SC1U10V2KX-1GP  [C402H22]  158.01 81.49 180 top
C7315  SC4D7U6D3V3KX-GP  [C603H36]  159.81 78.29 180 top
C7316  SCD1U25V2KX-GP  [C402H22]  168.19 81.94 270 top
C7317  SC4D7U6D3V3KX-GP  [C603H36]  147.34 85.18 180 bottom
C7318  SCD1U25V2KX-1-DL-GP  [C402H22]  156.74 84.29 0 top
C7319  SC1U10V2KX-1GP  [C402H22]  148.36 85.2 180 bottom
C7323  SC10U6D3V3MX-GP  [C603H38]  154.33 91.02 90 top
C7324  SC4D7U6D3V3KX-GP  [C603H36]  160.95 76.47 90 top
C7326  SC22U6D3V3MX-1-GP  [C603H40]  155.8 89.55 90 top
C7501  SCD1U25V2KX-1-DL-GP  [C402H22]  164.23 87.72 90 top
C7502  SCD1U25V2KX-1-DL-GP  [C402H22]  168.19 82.77 270 top
C7505  SCD1U25V2KX-1-DL-GP  [C402H22]  167.53 85.56 180 top
C7506  SCD1U25V2KX-1-DL-GP  [C402H22]  160.93 88.99 270 top
C7507  SC1U10V2KX-1DLGP  [C402H22]  165.25 101.56 90 top
C7513  SC4D7U6D3V3KX-GP  [C603H36]  159.79 87.97 90 top
C7514  SC4D7U6D3V3KX-GP  [C603H36]  162.2 87.97 270 top
C7517  SC10U6D3V3MX-GP  [C603H38]  194 98.49 270 bottom
C7518  SC22U6D3V3MX-1-GP  [C603H40]  147.34 87.59 0 bottom
C7520  SC22U6D3V3MX-1-GP  [C603H40]  157.63 88.99 180 top
C7525  SC1U10V2KX-1DLGP  [C402H22]  194 97.22 270 bottom
C7601  SCD1U25V2KX-1-DL-GP  [C402H22]  162.71 75.27 0 top
C7602  SCD1U25V2KX-1-DL-GP  [C402H22]  163.47 75.27 0 top
C7603  SC4D7U6D3V3KX-GP  [C603H36]  160.93 68.67 180 bottom
C7604  SC10U6D3V3MX-GP  [C603H38]  162.2 68.67 180 bottom
C7605  SCD1U25V2KX-1-DL-GP  [C402H22]  165.02 77.13 180 top
C7606  SC2D2U10V3KX-1DLGP-U  [C603H36]  165.37 75.2 0 top
C7607  SC18P50V2JN-1-GP  [C402H22]  178.84 78.45 90 bottom
C7608  SC18P50V2JN-1-GP  [C402H22]  176.55 78.45 90 bottom
C7701  SC4D7U6D3V3KX-GP  [C603H36]  161.82 83.53 0 top
C7702  SC4D7U6D3V3KX-GP  [C603H36]  161.82 86.07 0 top
C7703  SC4D7U6D3V3KX-GP  [C603H36]  167.53 75.53 0 top
C7704  SC4D7U6D3V3KX-GP  [C603H36]  170.4 78.23 0 top
C7708  SC4D7U6D3V3KX-GP  [C603H36]  163.14 78.47 0 top
C7709  SC4D7U6D3V3KX-GP  [C603H36]  159.79 86.07 0 top
C7710  SC22U6D3V3MX-1-GP  [C603H40]  161.87 78.47 0 top
C7711  SC1U10V2KX-1GP  [C402H22]  166.26 79.21 270 top
C7712  SC1U10V2KX-1GP  [C402H22]  164.92 78.6 0 top
C7713  SC1U10V2KX-1GP  [C402H22]  164.15 78.6 0 top
C7714  SC1U10V2KX-1GP  [C402H22]  160.85 78.6 0 top
C7717  SC22U6D3V3MX-1-GP  [C603H40]  159.79 81.11 0 top
C7719  SC4D7U6D3V3KX-GP  [C603H36]  165.76 83.53 0 top
C7720  SC4D7U6D3V3KX-GP  [C603H36]  165.76 86.07 0 top
C7721  SC4D7U6D3V3KX-GP  [C603H36]  163.72 81.11 0 top
C7722  SC4D7U6D3V3KX-GP  [C603H36]  163.72 83.53 0 top
C7723  SC4D7U6D3V3KX-GP  [C603H36]  161.82 81.11 0 top
C7724  SC4D7U6D3V3KX-GP  [C603H36]  163.72 86.07 0 top
C7725  SC4D7U6D3V3KX-GP  [C603H36]  165.76 81.11 0 top
C7726  SC4D7U6D3V3KX-GP  [C603H36]  156.23 87.34 180 top
C7728  SC1U10V2KX-1GP  [C402H22]  166.14 77.68 270 top
C7729  SCD1U25V2KX-1-DL-GP  [C402H22]  166.14 78.45 270 top
C7730  SC4D7U6D3V3KX-GP  [C603H36]  157.75 83.53 0 top
C7731  SC4D7U6D3V3KX-GP  [C603H36]  157.75 86.07 0 top
C7732  SC4D7U6D3V3KX-GP  [C603H36]  159.79 83.53 0 top
C7734  SCD1U25V2KX-1-DL-GP  [C402H22]  166.14 76.92 270 top
C7735  SCD1U25V2KX-1-DL-GP  [C402H22]  160.85 75.45 90 top
C7736  SC1U10V2KX-1GP  [C402H22]  167.41 80.61 180 top
C7801  SCD01U50V2KX-1DLGP  [C402H22]  188.42 109.66 180 top
C7802  SC820P50V2KX-1GP  [C402H22]  180.74 119.72 0 bottom
C7803  SC820P50V2KX-1GP  [C402H22]  186.77 112.92 0 top
C7804  SC10U6D3V3MX-GP  [C603H38]  169.06 103.12 270 top
C7805  SC1U50V3KX-GP  [C603H32]  169.06 101.81 270 top
C7806  SC1U50V3KX-GP  [C603H32]  161.69 121.5 180 top
C7807  SC1U50V3KX-GP  [C603H32]  147.59 116.55 270 top
C7808  SCD1U25V2KX-GP  [C402H22]  194.1 99.5 270 bottom
C7809  SC1U50V3KX-GP  [C603H32]  169.06 105.15 270 top
